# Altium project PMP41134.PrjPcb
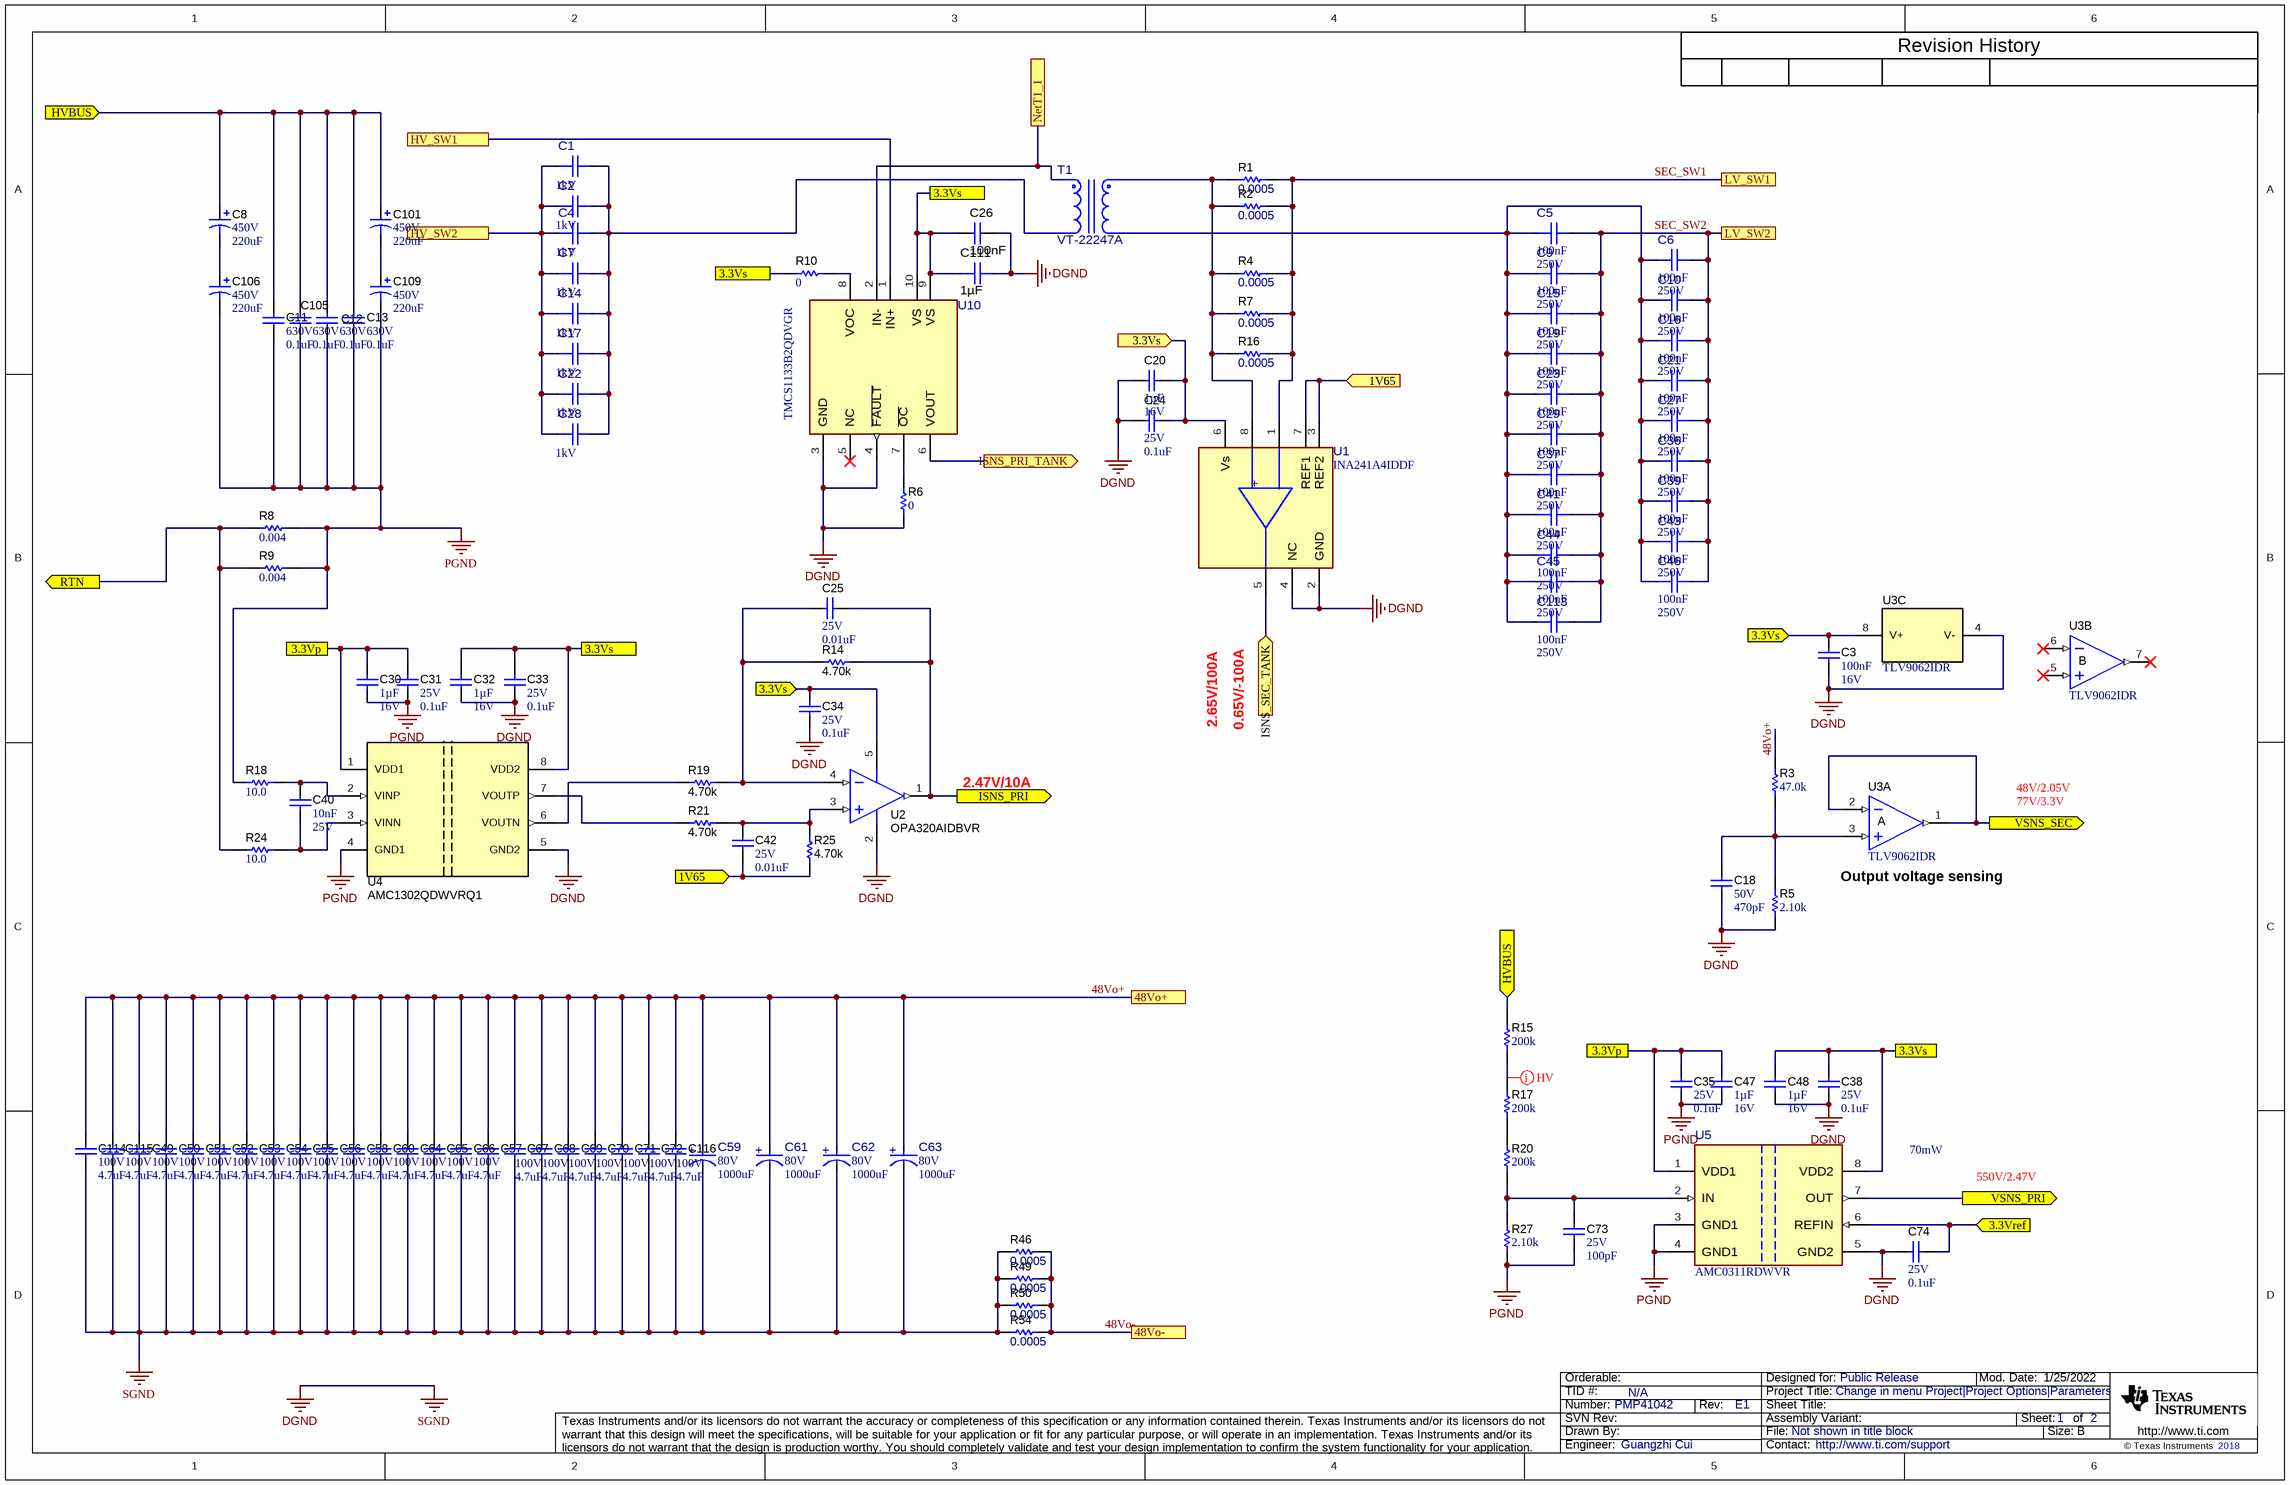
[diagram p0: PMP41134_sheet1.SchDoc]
CopyrightYear: 2018; PCB_Layout: Who did the Layout?; PCB_Rev: E1; PRJ_Customer: Public Release; PRJ_Engineer: Guangzhi Cui; PRJ_Number: PMP41042; PRJ_Title: Change in menu Project|Project Options|Parameters; SCH_Rev: E1; TechSupport: http://www.ti.com/support; TID: N/A
2 sheets, 222 parts. Net scope: flat (ports and power ports of the same name join across sheets).
Board file: PMP41134.PcbDoc
Sheets:
  PMP41134_sheet1.SchDoc
  PMP41134_sheet2.SchDoc

## Sheet PMP41134_sheet1.SchDoc
size 431 x 279 mm; Date: Not shown in title block; ApprovedBy: Not shown in title block; CheckedBy: Not shown in title block; Author: Not shown in title block; CompanyName: Not shown in title block; Engineer: Not shown in title block; Organization: Not shown in title block; Address1: Not shown in title block; Address2: Not shown in title block; Address3: Not shown in title block; Address4: Not shown in title block; DocumentNumber: 1; Revision: Use project parameter SCH_Rev; SheetNumber: 1; SheetTotal: 2; PageSetup: Record=PageOptions¦CenterHorizontal=True¦CenterVertical=True¦PrintScale=1.00¦XCorrection=1.00¦YCorrection=1.00¦PrintKind=0¦BorderSize=5000000¦LeftOffset=0¦BottomOffset=0¦Orientation=2¦PaperLength=1000¦PaperWidth=1000¦Scale=100¦PaperSource=15¦PrintQuality=600¦MediaType=1¦DitherType=10¦PaperKind=Letter¦PrintScaleMode=1

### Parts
C1  VDC_V: 1kV  [FP-C3225C0G3A472J200AC_1210-MFG]  (hidden comment: C3225C0G3A103J250AC)
C2  VDC_V: 1kV  [FP-C3225C0G3A472J200AC_1210-MFG]  (hidden comment: C3225C0G3A103J250AC)
C3  Cap_F: 100nF  VDC_V: 16V  [0603]  (hidden comment: CL10B104KO8NNNC)
C4  VDC_V: 1kV  [FP-C3225C0G3A472J200AC_1210-MFG]  (hidden comment: C3225C0G3A103J250AC)
C5  ValueDisplayed: 100nF  VDC_V: 250V  [FP-C4532C0G2E104J320KN_1812-MFG]  (hidden comment: C4532C0G2E104J320KN)
C6  ValueDisplayed: 100nF  VDC_V: 250V  [FP-C4532C0G2E104J320KN_1812-MFG]  (hidden comment: C4532C0G2E104J320KN)
C7  VDC_V: 1kV  [FP-C3225C0G3A472J200AC_1210-MFG]  (hidden comment: C3225C0G3A103J250AC)
C8  VDC_V: 450V  ValueDisplayed: 220uF  [QXW_1800x5000]  (hidden comment: 450QXW220MEFC18X50)
C9  ValueDisplayed: 100nF  VDC_V: 250V  [FP-C4532C0G2E104J320KN_1812-MFG]  (hidden comment: C4532C0G2E104J320KN)
C10  ValueDisplayed: 100nF  VDC_V: 250V  [FP-C4532C0G2E104J320KN_1812-MFG]  (hidden comment: C4532C0G2E104J320KN)
C11  VDC_V: 630V  ValueDisplayed: 0.1uF  [1210_200]  (hidden comment: CGA6L1X7T2J104K160AC)
C12  VDC_V: 630V  ValueDisplayed: 0.1uF  [1210_200]  (hidden comment: CGA6L1X7T2J104K160AC)
C13  VDC_V: 630V  ValueDisplayed: 0.1uF  [1210_200]  (hidden comment: CGA6L1X7T2J104K160AC)
C14  VDC_V: 1kV  [FP-C3225C0G3A472J200AC_1210-MFG]  (hidden comment: C3225C0G3A103J250AC)
C15  ValueDisplayed: 100nF  VDC_V: 250V  [FP-C4532C0G2E104J320KN_1812-MFG]  (hidden comment: C4532C0G2E104J320KN)
C16  ValueDisplayed: 100nF  VDC_V: 250V  [FP-C4532C0G2E104J320KN_1812-MFG]  (hidden comment: C4532C0G2E104J320KN)
C17  VDC_V: 1kV  [FP-C3225C0G3A472J200AC_1210-MFG]  (hidden comment: C3225C0G3A103J250AC)
C18  VDC_V: 50V  ValueDisplayed: 470pF  [0402]  (hidden comment: GRM1555C1H471JA01D)
C19  ValueDisplayed: 100nF  VDC_V: 250V  [FP-C4532C0G2E104J320KN_1812-MFG]  (hidden comment: C4532C0G2E104J320KN)
C20  Cap_F: 1µF  VDC_V: 16V  [0603]  (hidden comment: CGA3E1X7R1C105K080AC)
C21  ValueDisplayed: 100nF  VDC_V: 250V  [FP-C4532C0G2E104J320KN_1812-MFG]  (hidden comment: C4532C0G2E104J320KN)
C22  VDC_V: 1kV  [FP-C3225C0G3A472J200AC_1210-MFG]  (hidden comment: C3225C0G3A332J200AE)
C23  ValueDisplayed: 100nF  VDC_V: 250V  [FP-C4532C0G2E104J320KN_1812-MFG]  (hidden comment: C4532C0G2E104J320KN)
C24  VDC_V: 25V  ValueDisplayed: 0.1uF  [0402]  (hidden comment: GRM155R71E104KE14D)
C25  VDC_V: 25V  ValueDisplayed: 0.01uF  [0402]  (hidden comment: GCM155R71E103KA37D)
C26  Cap_F: 100nF  [0603]  (hidden comment: 06033C104KAT2A)
C27  ValueDisplayed: 100nF  VDC_V: 250V  [FP-C4532C0G2E104J320KN_1812-MFG]  (hidden comment: C4532C0G2E104J320KN)
C28  VDC_V: 1kV  [FP-C3225C0G3A472J200AC_1210-MFG]  (hidden comment: C3225C0G3A332J200AE)
C29  ValueDisplayed: 100nF  VDC_V: 250V  [FP-C4532C0G2E104J320KN_1812-MFG]  (hidden comment: C4532C0G2E104J320KN)
C30  Cap_F: 1µF  VDC_V: 16V  [0603]  (hidden comment: CGA3E1X7R1C105K080AC)
C31  VDC_V: 25V  ValueDisplayed: 0.1uF  [0402]  (hidden comment: GRM155R71E104KE14D)
C32  Cap_F: 1µF  VDC_V: 16V  [0603]  (hidden comment: CGA3E1X7R1C105K080AC)
C33  VDC_V: 25V  ValueDisplayed: 0.1uF  [0402]  (hidden comment: GRM155R71E104KE14D)
C34  VDC_V: 25V  ValueDisplayed: 0.1uF  [0402]  (hidden comment: GRM155R71E104KE14D)
C35  VDC_V: 25V  ValueDisplayed: 0.1uF  [0402]  (hidden comment: GRM155R71E104KE14D)
C36  ValueDisplayed: 100nF  VDC_V: 250V  [FP-C4532C0G2E104J320KN_1812-MFG]  (hidden comment: C4532C0G2E104J320KN)
C37  ValueDisplayed: 100nF  VDC_V: 250V  [FP-C4532C0G2E104J320KN_1812-MFG]  (hidden comment: C4532C0G2E104J320KN)
C38  VDC_V: 25V  ValueDisplayed: 0.1uF  [0402]  (hidden comment: GRM155R71E104KE14D)
C39  ValueDisplayed: 100nF  VDC_V: 250V  [FP-C4532C0G2E104J320KN_1812-MFG]  (hidden comment: C4532C0G2E104J320KN)
C40  Cap_F: 10nF  VDC_V: 25V  [0603]  (hidden comment: GRM188R71E103KA01D)
C41  ValueDisplayed: 100nF  VDC_V: 250V  [FP-C4532C0G2E104J320KN_1812-MFG]  (hidden comment: C4532C0G2E104J320KN)
C42  VDC_V: 25V  ValueDisplayed: 0.01uF  [0402]  (hidden comment: GCM155R71E103KA37D)
C43  ValueDisplayed: 100nF  VDC_V: 250V  [FP-C4532C0G2E104J320KN_1812-MFG]  (hidden comment: C4532C0G2E104J320KN)
C44  ValueDisplayed: 100nF  VDC_V: 250V  [FP-C4532C0G2E104J320KN_1812-MFG]  (hidden comment: C4532C0G2E104J320KN)
C45  ValueDisplayed: 100nF  VDC_V: 250V  [FP-C4532C0G2E104J320KN_1812-MFG]  (hidden comment: C4532C0G2E104J320KN)
C46  ValueDisplayed: 100nF  VDC_V: 250V  [FP-C4532C0G2E104J320KN_1812-MFG]  (hidden comment: C4532C0G2E104J320KN)
C47  Cap_F: 1µF  VDC_V: 16V  [0603]  (hidden comment: CGA3E1X7R1C105K080AC)
C48  Cap_F: 1µF  VDC_V: 16V  [0603]  (hidden comment: CGA3E1X7R1C105K080AC)
C49  VDC_V: 100V  ValueDisplayed: 4.7uF  [1206_180]  (hidden comment: GRM31CZ72A475KE11L)
C50  VDC_V: 100V  ValueDisplayed: 4.7uF  [1206_180]  (hidden comment: GRM31CZ72A475KE11L)
C51  VDC_V: 100V  ValueDisplayed: 4.7uF  [1206_180]  (hidden comment: GRM31CZ72A475KE11L)
C52  VDC_V: 100V  ValueDisplayed: 4.7uF  [1206_180]  (hidden comment: GRM31CZ72A475KE11L)
C53  VDC_V: 100V  ValueDisplayed: 4.7uF  [1206_180]  (hidden comment: GRM31CZ72A475KE11L)
C54  VDC_V: 100V  ValueDisplayed: 4.7uF  [1206_180]  (hidden comment: GRM31CZ72A475KE11L)
C55  VDC_V: 100V  ValueDisplayed: 4.7uF  [1206_180]  (hidden comment: GRM31CZ72A475KE11L)
C56  VDC_V: 100V  ValueDisplayed: 4.7uF  [1206_180]  (hidden comment: GRM31CZ72A475KE11L)
C57  GRM31CR72A225KA73L  [1206_190]  (value not drawn)
C58  VDC_V: 100V  ValueDisplayed: 4.7uF  [1206_180]  (hidden comment: GRM31CZ72A475KE11L)
C59  VDC_V: 80V  ValueDisplayed: 1000uF  [FP-EGPD800ELL102ML35H_RADIAL-MFG]  (hidden comment: EGPD800ELL102ML35H)
C60  VDC_V: 100V  ValueDisplayed: 4.7uF  [1206_180]  (hidden comment: GRM31CZ72A475KE11L)
C61  VDC_V: 80V  ValueDisplayed: 1000uF  [FP-EGPD800ELL102ML35H_RADIAL-MFG]  (hidden comment: EGPD800ELL102ML35H)
C62  VDC_V: 80V  ValueDisplayed: 1000uF  [FP-EGPD800ELL102ML35H_RADIAL-MFG]  (hidden comment: EGPD800ELL102ML35H)
C63  VDC_V: 80V  ValueDisplayed: 1000uF  [FP-EGPD800ELL102ML35H_RADIAL-MFG]  (hidden comment: EGPD800ELL102ML35H)
C64  VDC_V: 100V  ValueDisplayed: 4.7uF  [1206_180]  (hidden comment: GRM31CZ72A475KE11L)
C65  VDC_V: 100V  ValueDisplayed: 4.7uF  [1206_180]  (hidden comment: GRM31CZ72A475KE11L)
C66  VDC_V: 100V  ValueDisplayed: 4.7uF  [1206_180]  (hidden comment: GRM31CZ72A475KE11L)
C67  VDC_V: 100V  ValueDisplayed: 4.7uF  [1206_180]  (hidden comment: GRM31CZ72A475KE11L)
C68  VDC_V: 100V  ValueDisplayed: 4.7uF  [1206_180]  (hidden comment: GRM31CZ72A475KE11L)
C69  VDC_V: 100V  ValueDisplayed: 4.7uF  [1206_180]  (hidden comment: GRM31CZ72A475KE11L)
C70  VDC_V: 100V  ValueDisplayed: 4.7uF  [1206_180]  (hidden comment: GRM31CZ72A475KE11L)
C71  VDC_V: 100V  ValueDisplayed: 4.7uF  [1206_180]  (hidden comment: GRM31CZ72A475KE11L)
C72  VDC_V: 100V  ValueDisplayed: 4.7uF  [1206_180]  (hidden comment: GRM31CZ72A475KE11L)
C73  VDC_V: 25V  ValueDisplayed: 100pF  [0402]  (hidden comment: C0402C101J3GACTU)
C74  VDC_V: 25V  ValueDisplayed: 0.1uF  [0402]  (hidden comment: GRM155R71E104KE14D)
C101  VDC_V: 450V  ValueDisplayed: 220uF  [QXW_1800x5000]  (hidden comment: 450QXW220MEFC18X50)
C105  VDC_V: 630V  ValueDisplayed: 0.1uF  [1210_200]  (hidden comment: CGA6L1X7T2J104K160AC)
C106  VDC_V: 450V  ValueDisplayed: 220uF  [QXW_1800x5000]  (hidden comment: 450QXW220MEFC18X50)
C109  VDC_V: 450V  ValueDisplayed: 220uF  [QXW_1800x5000]  (hidden comment: 450QXW220MEFC18X50)
C111  Cap_F: 1µF  [FP-CL10B105KA8VPJC_0603-MFG]  (hidden comment: CL10B105KA8VPJC)
C113  ValueDisplayed: 100nF  VDC_V: 250V  [FP-C4532C0G2E104J320KN_1812-MFG]  (hidden comment: C4532C0G2E104J320KN)
C114  VDC_V: 100V  ValueDisplayed: 4.7uF  [1206_180]  (hidden comment: GRM31CZ72A475KE11L)
C115  VDC_V: 100V  ValueDisplayed: 4.7uF  [1206_180]  (hidden comment: GRM31CZ72A475KE11L)
C116  VDC_V: 100V  ValueDisplayed: 4.7uF  [1206_180]  (hidden comment: GRM31CZ72A475KE11L)
R1  ValueDisplayed: 0.0005  [2512]  (hidden comment: CSNL2512FTL500)
R2  ValueDisplayed: 0.0005  [2512]  (hidden comment: CSNL2512FTL500)
R3  ValueDisplayed: 47.0k  [0603]  (hidden comment: CRCW060347K0FKEA)
R4  ValueDisplayed: 0.0005  [2512]  (hidden comment: CSNL2512FTL500)
R5  ValueDisplayed: 2.10k  [0603]  (hidden comment: RT0603BRD072K1L)
R6  ValueDisplayed: 0  [0603]  (hidden comment: MCT06030Z0000ZP500)
R7  ValueDisplayed: 0.0005  [2512]  (hidden comment: CSNL2512FTL500)
R8  ValueDisplayed: 0.004  [1206]  (hidden comment: CRF1206-FZ-R004ELF)
R9  ValueDisplayed: 0.004  [1206]  (hidden comment: CRF1206-FZ-R004ELF)
R10  ValueDisplayed: 0  [0603]  (hidden comment: MCT06030Z0000ZP500)
R14  ValueDisplayed: 4.70k  [0402]  (hidden comment: RC0402FR-074K7L)
R15  ValueDisplayed: 200k  [1206]  (hidden comment: ERJ-8ENF2003V)
R16  ValueDisplayed: 0.0005  [2512]  (hidden comment: CSNL2512FTL500)
R17  ValueDisplayed: 200k  [1206]  (hidden comment: ERJ-8ENF2003V)
R18  ValueDisplayed: 10.0  [0603]  (hidden comment: CRCW060310R0FKEA)
R19  ValueDisplayed: 4.70k  [0402]  (hidden comment: RC0402FR-074K7L)
R20  ValueDisplayed: 200k  [1206]  (hidden comment: ERJ-8ENF2003V)
R21  ValueDisplayed: 4.70k  [0402]  (hidden comment: RC0402FR-074K7L)
R24  ValueDisplayed: 10.0  [0603]  (hidden comment: CRCW060310R0FKEA)
R25  ValueDisplayed: 4.70k  [0402]  (hidden comment: RC0402FR-074K7L)
R27  ValueDisplayed: 2.10k  [0603]  (hidden comment: RT0603BRD072K1L)
R46  ValueDisplayed: 0.0005  [2512]  (hidden comment: CSNL2512FTL500)
R49  ValueDisplayed: 0.0005  [2512]  (hidden comment: CSNL2512FTL500)
R50  ValueDisplayed: 0.0005  [2512]  (hidden comment: CSNL2512FTL500)
R54  ValueDisplayed: 0.0005  [2512]  (hidden comment: CSNL2512FTL500)
T1  VT-22247A  [FP-VT-22247A_XFRMR_70MM0_63MM0-MFG]
U1  INA241A4IDDF  [DDF0008A-MFG]
U2  OPA320AIDBVR  [DBV0005A_N]
U3  TLV9062IDR  [D0008A_N]  (parts A,B,C of 3)
U4  AMC1302QDWVRQ1  [DWV0008A]
U5  AMC0311RDWVR  [DWV0008A-MFG]
U10  TMCS1133B2QDVGR  [DVG0010A-MFG]

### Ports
1V65 (in), 3.3Vp, 3.3Vref (in), 3.3Vs, 3.3Vs (in), 48Vo+, 48Vo-, HV_SW1, HV_SW2, HVBUS (in), ISNS_PRI (out), ISNS_PRI_TANK (out), ISNS_SEC_TANK (in), LV_SW1, LV_SW2, NetT1_1, RTN (out), VSNS_PRI (out), VSNS_SEC (out)

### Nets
PGND: C11.2 C12.2 C13.2 C30.2 C31.2 C35.2 C47.2 C73.2 C105.2 C106.2(-) C109.2(-) R8.2 R9.2 R18.1 R27.1 U4.4(GND1) U5.3(GND1) U5.4(GND1)
SGND: C3.2 C18.2 C20.2 C24.2 C26.2 C32.2 C33.2 C34.2 C38.2 C48.2 C49.2 C50.2 C51.2 C52.2 C53.2 C54.2 C55.2 C56.2 C57.2 C58.2 C59.1(CATHODE) C60.2 C61.1(CATHODE) C62.1(CATHODE) C63.1(CATHODE) C64.2 C65.2 C66.2 C67.2 C68.2 C69.2 C70.2 C71.2 C72.2 C74.1 C111.2 C114.2 C115.2 C116.2 R5.1 R6.1 R46.1 R49.1 R50.1 R54.1 U1.2(GND) U1.4(NC) U2.2(V-) U3.4(V-) U4.5(GND2) U5.5(GND2) U10.3(GND) U10.4(~{FAULT})  [also labelled DGND]
1V65: C42.2 R25.1 U1.3(REF2) U1.7(REF1) ; port 1V65
3.3Vp: C30.1 C31.1 C35.1 C47.1 U4.1(VDD1) U5.1(VDD1) ; port 3.3Vp
3.3Vref: C74.2 U5.6(REFIN) ; port 3.3Vref
3.3Vs: C3.1 C20.1 C24.1 C26.1 C32.1 C33.1 C34.1 C38.1 C48.1 C111.1 R10.2 U1.6(Vs) U2.5(V+) U3.8(V+) U4.8(VDD2) U5.8(VDD2) U10.9(VS) U10.10(VS) ; port 3.3Vs
48Vo+: C49.1 C50.1 C51.1 C52.1 C53.1 C54.1 C55.1 C56.1 C57.1 C58.1 C59.2(ANODE) C60.1 C61.2(ANODE) C62.2(ANODE) C63.2(ANODE) C64.1 C65.1 C66.1 C67.1 C68.1 C69.1 C70.1 C71.1 C72.1 C114.1 C115.1 C116.1 R3.2 ; port 48Vo+
48Vo-: R46.2 R49.2 R50.2 R54.2 ; port 48Vo-
HV_SW1: U10.1(IN+) ; port HV_SW1
HV_SW2: C1.1 C2.1 C4.1 C7.1 C14.1 C17.1 C22.1 C28.1 ; port HV_SW2
HVBUS: C8.1(+) C11.1 C12.1 C13.1 C101.1(+) C105.1 R15.2 ; port HVBUS
ISNS_PRI: C25.1 R14.2 U2.1(OUT) ; port ISNS_PRI
ISNS_PRI_TANK: U10.6(VOUT) ; port ISNS_PRI_TANK
ISNS_SEC_TANK: U1.5(OUT) ; port ISNS_SEC_TANK
NetT1_1: U10.2(IN-) ; port NetT1_1
RTN: R8.1 R9.1 R24.1 ; port RTN
SEC_SW1: R1.2 R2.2 R4.2 R7.2 R16.2 U1.1(IN-) ; port LV_SW1
SEC_SW2: C5.2 C6.2 C9.2 C10.2 C15.2 C16.2 C19.2 C21.2 C23.2 C27.2 C29.2 C36.2 C37.2 C39.2 C41.2 C43.2 C44.2 C45.2 C46.2 C113.2 ; port LV_SW2
VSNS_PRI: U5.7(OUT) ; port VSNS_PRI
VSNS_SEC: U3.1(OUT) U3.2(IN-) ; port VSNS_SEC
NetC1_2: C1.2 C2.2 C4.2 C7.2 C14.2 C17.2 C22.2 C28.2
NetC5_1: C5.1 C6.1 C9.1 C10.1 C15.1 C16.1 C19.1 C21.1 C23.1 C27.1 C29.1 C36.1 C37.1 C39.1 C41.1 C43.1 C44.1 C45.1 C46.1 C113.1
NetC8_2: C8.2(-) C106.1(+)
NetC18_1: C18.1 R3.1 R5.2 U3.3(IN+)
NetC25_2: C25.2 R14.1 R19.2 U2.4(IN-)
NetC40_1: C40.1 R18.2 U4.2(VINP)
NetC40_2: C40.2 R24.2 U4.3(VINN)
NetC42_1: C42.1 R21.2 R25.2 U2.3(IN+)
NetC73_1: C73.1 R20.1 R27.2 U5.2(IN)
NetC101_2: C101.2(-) C109.1(+)
NetR1_1: R1.1 R2.1 R4.1 R7.1 R16.1 U1.8(IN+)
NetR6_2: R6.2 U10.7(~{OC})
NetR10_1: R10.1 U10.8(VOC)
NetR15_1: R15.1 R17.2
NetR17_1: R17.1 R20.2
NetR19_1: R19.1 U4.6(VOUTN)
NetR21_1: R21.1 U4.7(VOUTP)

Not connected (* = marked no-connect by the designer): U3 5(IN+)* 6(IN-)* 7(OUT)*; U10 5(NC)*

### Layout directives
net class MV: NetR15_1

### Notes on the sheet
- Revision History
- 2.65V/100A
- 0.65V/-100A
- 2.47V/10A
- 77V/3.3V
- 48V/2.05V
- (near U3) Output voltage sensing
- 70mW
- 550V/2.47V

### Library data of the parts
C1 C2 C4 C7 C14 C17 = CMP-0121422-1: Multilayer Ceramic Capacitors 10nF ±5% 1000V C0G SMD 1210; Manufacturer: TDK; AEC Qualified: No; SizeZ_mm: 2.2mm; TempCo: 30ppm/°C; Tolerance_%: 0.05%
C3 = CMP-0007110-5: CAP, CERM, 0.1 uF, 16 V, +/- 10%, X7R, 0603; Manufacturer: Samsung Electro-Mechanics; TaMin_C: -55°C; Polarized: N; SizeAreaWB_mm2: 4.68; Value1: Unknown; U/M: EA; Value: 0.1uF; TaMax_C: 125°C; SizeZ_mm: 1; SizeX_mm: 1.6; SizeY_mm: 0.8; SizeArea_mm2: 1.28; AEC Category: Q200
C5 C6 C9 C10 C15 C16 C19 C21 C23 C27 C29 C36 C37 C39 C41 C43-C46 C113 = CMP-0097363-1: Multilayer Ceramic Capacitors 100nF ±5% 250V C0G SMD 1812; Manufacturer: TDK; SizeZ_mm: 3.5mm; TempCo: 30ppm/°C; Tolerance_%: 0.05%; AEC Qualified: No
C8 C101 C106 C109 = CMP-0009981-2: CAP, AL, 220 uF, 450 V, +/- 20%, TH; Manufacturer: Rubycon; TaMin_C: -40°C; Polarized: Y; SizeAreaWB_mm2: 400; Value1: Unknown; U/M: EA; Value: 220uF; TaMax_C: 105°C; SizeZ_mm: 52; SizeX_mm: 18; Cap_Case: 18x50mm; SizeArea_mm2: 324; CompType: Capacitor; AEC Qualified: N; Cap_F: 220µF; IRMS_A: 1.22A; AEC Category: Q200
C11-C13 C105 = CMP-0009140-2: CAP, CERM, 0.1 uF, 630 V, +/- 10%, X7R, AEC-Q200 Grade 1, 1210; Manufacturer: TDK; TaMin_C: -55°C; Polarized: N; SizeAreaWB_mm2: 14.7; Value1: Unknown; U/M: EA; Value: 0.1uF; TaMax_C: 125°C; SizeZ_mm: 2; SizeX_mm: 3.2; SizeY_mm: 2.5; Cap_Case: 1210; SizeArea_mm2: 8; AEC Qualified: Y; Cap_F: 100nF; AEC Grade: 1; AEC Category: Q200
C18 = CMP-0006470-1: CAP, CERM, 470 pF, 50 V, +/- 5%, C0G/NP0, 0402; Manufacturer: MuRata; TaMin_C: -55°C; Polarized: N; SizeAreaWB_mm2: 3; Value1: Unknown; U/M: EA; Value: 470pF; TaMax_C: 125°C; SizeZ_mm: 0.6; SizeX_mm: 1; SizeY_mm: 0.5; AEC Category: Q200
C20 C30 C32 C47 C48 = CMP-0079607-1: CAP, CERM, 1 µF, 16 V,+/- 10%, X7R, AEC-Q200 Grade 1, 0603; Manufacturer: TDK; TaMin_C: -55°C; Polarized: N; SizeAreaWB_mm2: 4.68; U/M: EA; Value: 1uF; TaMax_C: 125°C; SizeZ_mm: 1; SizeX_mm: 1.6; SizeY_mm: 0.8; SizeArea_mm2: 1.28; AEC Qualified: Y; AEC Category: Q200
C22 = CMP-0121422-1: Multilayer Ceramic Capacitors 3.3nF ±5% 1000V C0G SMD 1210; Manufacturer: TDK; AEC Qualified: No; SizeZ_mm: 2.2mm; TempCo: 30ppm/°C; Tolerance_%: 0.05%
C24 C31 C33-C35 C38 C74 = CMP-0006659-2: CAP, CERM, 0.1 uF, 25 V, +/- 10%, X7R, 0402; Manufacturer: MuRata; TaMin_C: -55°C; Polarized: N; SizeAreaWB_mm2: 3; Value1: Unknown; U/M: EA; Value: 0.1uF; TaMax_C: 125°C; SizeZ_mm: 0.6; SizeX_mm: 1; SizeY_mm: 0.5; Cap_F: 100nF; AEC Category: Q200
C25 C42 = CMP-0006352-2: CAP, CERM, 0.01 uF, 25 V, +/- 10%, X7R, 0402; Manufacturer: MuRata; TaMin_C: -55°C; Polarized: N; SizeAreaWB_mm2: 3; Value1: Unknown; U/M: EA; Value: 0.01uF; TaMax_C: 125°C; SizeZ_mm: 0.6; SizeX_mm: 1; SizeY_mm: 0.5; Cap_F: 10nF; AEC Category: Q200
C26 = CMP-0006753-4: CAP, CERM, 0.1 uF, 25 V, +/- 10%, X7R, 0603; Manufacturer: AVX; TaMin_C: -55°C; ESR_ohm: 0.05; Polarized: N; SizeAreaWB_mm2: 4.68; Value1: 0.05 ohm; U/M: EA; Value: 0.1uF; TaMax_C: 125°C; SizeZ_mm: 1; SizeX_mm: 1.6; SizeY_mm: 0.8; Value2: 25V; SizeArea_mm2: 1.28; AEC Category: Q200
C28 = CMP-0121422-1: Multilayer Ceramic Capacitors 3.3nF ±5% 1000V C0G SMD 1210; Manufacturer: TDK; Part Number: C3225C0G3A472J200AC; AEC Qualified: No; Cap_F: 4.7nF; SizeZ_mm: 2.2mm; TempCo: 30ppm/°C; Tolerance_%: 0.05%
C40 = CMP-0007403-4: CAP, CERM, 0.01 uF, 25 V, +/- 10%, X7R, 0603; Manufacturer: MuRata; TaMin_C: -55°C; Polarized: N; SizeAreaWB_mm2: 4.68; Value1: Unknown; U/M: EA; Value: 0.01uF; TaMax_C: 125°C; SizeZ_mm: 1; SizeX_mm: 1.6; SizeY_mm: 0.8; SizeArea_mm2: 1.28; AEC Category: Q200
C49-C56 C58 C60 C64-C72 C114-C116 = CMP-0008802-2: CAP, CERM, 4.7 uF, 100 V, +/- 10%, X7R, 1206; Manufacturer: Samsung; TaMin_C: -55°C; Polarized: N; SizeAreaWB_mm2: 10.92; Value1: Unknown; U/M: EA; Value: 4.7uF; TaMax_C: 125°C; SizeZ_mm: 1.8; SizeX_mm: 3.2; SizeY_mm: 1.6; Cap_Case: 1206; SizeArea_mm2: 5.12; Cap_F: 4.7µF; AEC Category: Q200
C57 = CMP-0008971-1: CAP, CERM, 2.2 uF, 100 V, +/- 10%, X7R, 1206_190; Manufacturer: MuRata; TaMin_C: -55°C; Polarized: N; SizeAreaWB_mm2: 10.92; Value1: Unknown; U/M: EA; Value: 2.2uF; TaMax_C: 125°C; SizeZ_mm: 1.9; SizeX_mm: 3.2; SizeY_mm: 1.6; Cap_Case: 1206; Value2: 100V; SizeArea_mm2: 5.12; Cap_F: 2.2µF; AEC Category: Q200
C59 C61-C63 = CMP-0097417-1: 1000 µF 80 V Aluminum Electrolytic Capacitors Radial, Can 27mOhm @ 100kHz 2000 Hrs @ 135°C; Manufacturer: United Chemi-Con; AEC Grade: Grade 0; Value: 1mF; Leakage Current: 2400uA; AEC Qualified: Yes; IRMS_A: 4.59A; Tolerance_%: 20%; Dissipation Factor: 8%; Life: 2000Hours; SizeZ_mm: 36.5mm; Esr: 27m
C73 = CMP-0006233-2: CAP, CERM, 100 pF, 25 V, +/- 5%, C0G/NP0, 0402; Manufacturer: Kemet; TaMin_C: -55°C; Polarized: N; SizeAreaWB_mm2: 3; Value1: Unknown; U/M: EA; Value: 100pF; TaMax_C: 125°C; SizeZ_mm: 0.6; SizeX_mm: 1; SizeY_mm: 0.5; AEC Category: Q200
C111 = CMP-0121052-1: Cap Ceramic 1uF 25V X7R ±10% Pad SMD 0603 +125°C T/R; Manufacturer: Samsung; AEC Grade: Grade 1; AEC Qualified: Yes; SizeZ_mm: 0.9mm; TempCo: 15%; Value: 1µF
R1 R2 R4 R7 R16 R46 R49 R50 R54 = CMP-0015817-2: RES, 0.0005, 1%, 2 W, 2512; Manufacturer: Stackpole Electronics Inc; Power_W: 3W; TempCo: ppm/C; Value_Code: 1L000; U/M: EA; Value: 0.0005; EIA_Code: E96; Res_ohm: 1m; SizeX_mm: 6.3; SizeY_mm: 3.2; SizeZ_mm: 0.71; Value2: 2W; SizeArea_mm2: 20.16; AEC Category: Q200
R3 = CMP-0022438-1: RES, 47.0 k, 1%, 0.1 W, AEC-Q200 Grade 0, 0603; Manufacturer: Vishay-Dale; Power_W: 100mW; TempCo: 100 ppm/C; Value_Code: 47k0; U/M: EA; Value: 47.0k; Res_ohm: 47k; SizeX_mm: 1.6; SizeY_mm: 0.8; SizeZ_mm: 1; Value2: 0.1W; SizeArea_mm2: 1.28; AEC Qualified: Y; VDC_V: 75V; AEC Grade: 0; AEC Category: Q200
R5 R27 = CMP-0024062-3: RES, 2.10 k, 0.1%, 0.1 W, 0603; Manufacturer: Yageo America; Power_W: 100mW; TempCo: 25 ppm/C; Value_Code: 2k10; U/M: EA; Value: 2.10k; EIA_Code: E192; Res_ohm: 2.1k; SizeX_mm: 1.6; SizeY_mm: 0.8; SizeZ_mm: 1; Value2: 0.1W; SizeArea_mm2: 1.28; VDC_V: 75V; AEC Category: Q200
R6 R10 = CMP-0025884-2: RES, 0, 5%, 0.125 W, 0603; Manufacturer: Vishay/Beyschlag; Power_W: 125mW; TempCo: ppm/C; Value_Code: 0000; U/M: EA; Value: 0; EIA_Code: E24; SizeX_mm: 1.6; SizeY_mm: 0.8; SizeZ_mm: 1; Value2: 0.125W; SizeArea_mm2: 1.28; AEC Qualified: N; AEC Category: Q200
R8 R9 = CMP-0078823-1: RES, 0.004, 1%, 1 W, AEC-Q200 Grade 0, 1206; Manufacturer: Bourns; Value_Code: 4L000; SizeArea_mm2: 5.12; AEC Qualified: Y; AEC Category: Q200; Res_ohm: 4m; Value: 0.004; SizeZ_mm: 1.35; TempCo: 50 ppm/C; AEC Grade: 0; SizeY_mm: 1.6; Power_W: 1W; SizeX_mm: 3.2
R14 R19 R21 R25 = CMP-0026739-1: RES, 4.70 k, 1%, 0.0625 W, 0402; Manufacturer: Yageo America; Power_W: 62.5mW; TempCo: 100 ppm/C; Value_Code: 4k70; U/M: EA; Value: 4.70k; Res_ohm: 4.7k; SizeX_mm: 1; SizeY_mm: 0.5; SizeZ_mm: 0.6; CompType: Resistor; AEC Qualified: N; VDC_V: 50V; AEC Category: Q200
R15 R17 R20 = CMP-0017437-1: RES, 200 k, 1%, 0.25 W, 1206; Manufacturer: Panasonic; Power_W: 250mW; TempCo: 100 ppm/C; U/M: EA; Value: 200k; EIA_Code: E96; SizeX_mm: 3.2; SizeY_mm: 1.6; SizeZ_mm: 1.35; Value2: 0.25W; SizeArea_mm2: 5.12; VDC_V: 200V; AEC Category: Q200
R18 R24 = CMP-0022003-4: RES, 10.0, 1%, 0.1 W, AEC-Q200 Grade 0, 0603; Manufacturer: Vishay-Dale; Power_W: 100mW; TempCo: 100 ppm/C; Value_Code: 10R0; Value: 10.0; EIA_Code: E96; Res_ohm: 10; SizeX_mm: 1.6; SizeY_mm: 0.8; SizeZ_mm: 1; Value2: 0.1W; SizeArea_mm2: 1.28; AEC Qualified: Y; VDC_V: 75V; AEC Category: Q200; AEC Grade: 0
T1 = CMP-0097657-1: Transformer 25:3 70x63x51mm; Manufacturer: Cyntec; SizeZ_mm: 51mm; DCR_ohm: 27m; Rsec1_ohm: 850µ; AEC Qualified: No; Ind_H: 47.4µH
U1 = CMP-0093650-2: -4-V to 110-V, Bidirectional, Ultra-Precise Current Sense Amplifier With Enhanced PWM Rejection; Manufacturer: Texas Instruments; Input Bias Current: 40uA; Response Time: 1.5us; TaMax_C: +125°C; Min Supply Voltage: 2.7V; Bandwidth: 1MHz; SizeZ_mm: 1.1mm; Number Of Channels: 1; Standoff Height: 0mm; Max Supply Voltage: 20V; Input Offset Voltage: 0.002mV; TJmax_C: +150°C; AEC Category: Q200; CompType: IC; TaMin_C: -40°C; Voltage Gain: 0.1V/mV; AEC Qualified: No; Nominal Supply Current: 2.5mA
U2 = CMP-0040888-1: Precision, 20 MHz, 0.9 pA Ib, RRIO, CMOS Operational Amplifier, 1.8 to 5.5 V, -40 to 125 degC, 5-pin SOT23 (DBV5), Green (RoHS & no Sb/Br); Manufacturer: Texas Instruments; CMRR(Min)(dB): 100; Iq per channel(Max)(mA): 1.75; IIB(Max)(pA): 0.9; Total Supply Voltage(Min)(+5V is 5, +/-5V is 10): 1.8; Sub Family: High Output Current Amplifier (>=50mA), Low Input Bias Current Amp (<=10pA), Low Noise Amp (<=10nV/rtHz), Low Offset Voltage Amplifier (<=500uV), Low Supply Voltage Amplifier (<=2.7V), Precision Amplifier; Number of Channels: 2; Total Supply Voltage(Max)(+5V is 5, +/-5V is 10): 5.5; Offset Drift(Typ)(uV/C): 1.5; Vn at 1kHz(Typ)(nV/rtHz): 8.5; Slew Rate(Typ)(V/us): 10; Vio (25C)(Max)(mV): 0.15
U3 = CMP-0013007-4: 10-MHz, Low-Noise, RRIO, CMOS Operational Amplifier for Cost-Sensitive Systems, D0008A (SOIC-8); Manufacturer: Texas Instruments; SizeX_mm: 4.9; SizeY_mm: 6.2; CompType: IC; SizeZ_mm: 1.75; SizeArea_mm2: 30.38; SizeAreaWB_mm2: 56.58; AEC Category: Q200; AEC Qualified: N; Rating: Catalog
U4 = CMP-0080587-1: Precision Reinforced Isolated Amplifier for Current Sensing, DWV0008A (SOIC-8); Alternate Manufacturer: Texas Instruments; SizeAreaWB_mm2: 105.975; SizeZ_mm: 2.8; SizeX_mm: 11.5; SizeY_mm: 5.85; SizeArea_mm2: 67.275; CompType: IC; AEC Qualified: Y; AEC Category: Q200
U5 = CMP-0122957-1: Automotive, Precision, 2-V Input, Basic and Reinforced Isolated Amplifiers With Single-Ended, Ratiometric Output; Manufacturer: Texas Instruments; SizeZ_mm: 2.8mm; AEC Qualified: No; Bandwidth: 110kHz; Input Bias Current: 0.0035uA; Input Offset Voltage: 0.4mV; Max Supply Voltage: 5.5V; Min Supply Voltage: 3V; Number Of Channels: 1; Output Current Per Channel: 14mA; Response Time: 500us; Standoff Height: 0.36mm; TaMax_C: +125°C; TaMin_C: -40°C; TJmax_C: +150°C
U10 = CMP-0097985-1: Manufacturer: Texas Instruments; SizeZ_mm: 2.65mm; Standoff Height: 0.1mm

## Sheet PMP41134_sheet2.SchDoc
size A2; SheetNumber: 2; SheetTotal: 2
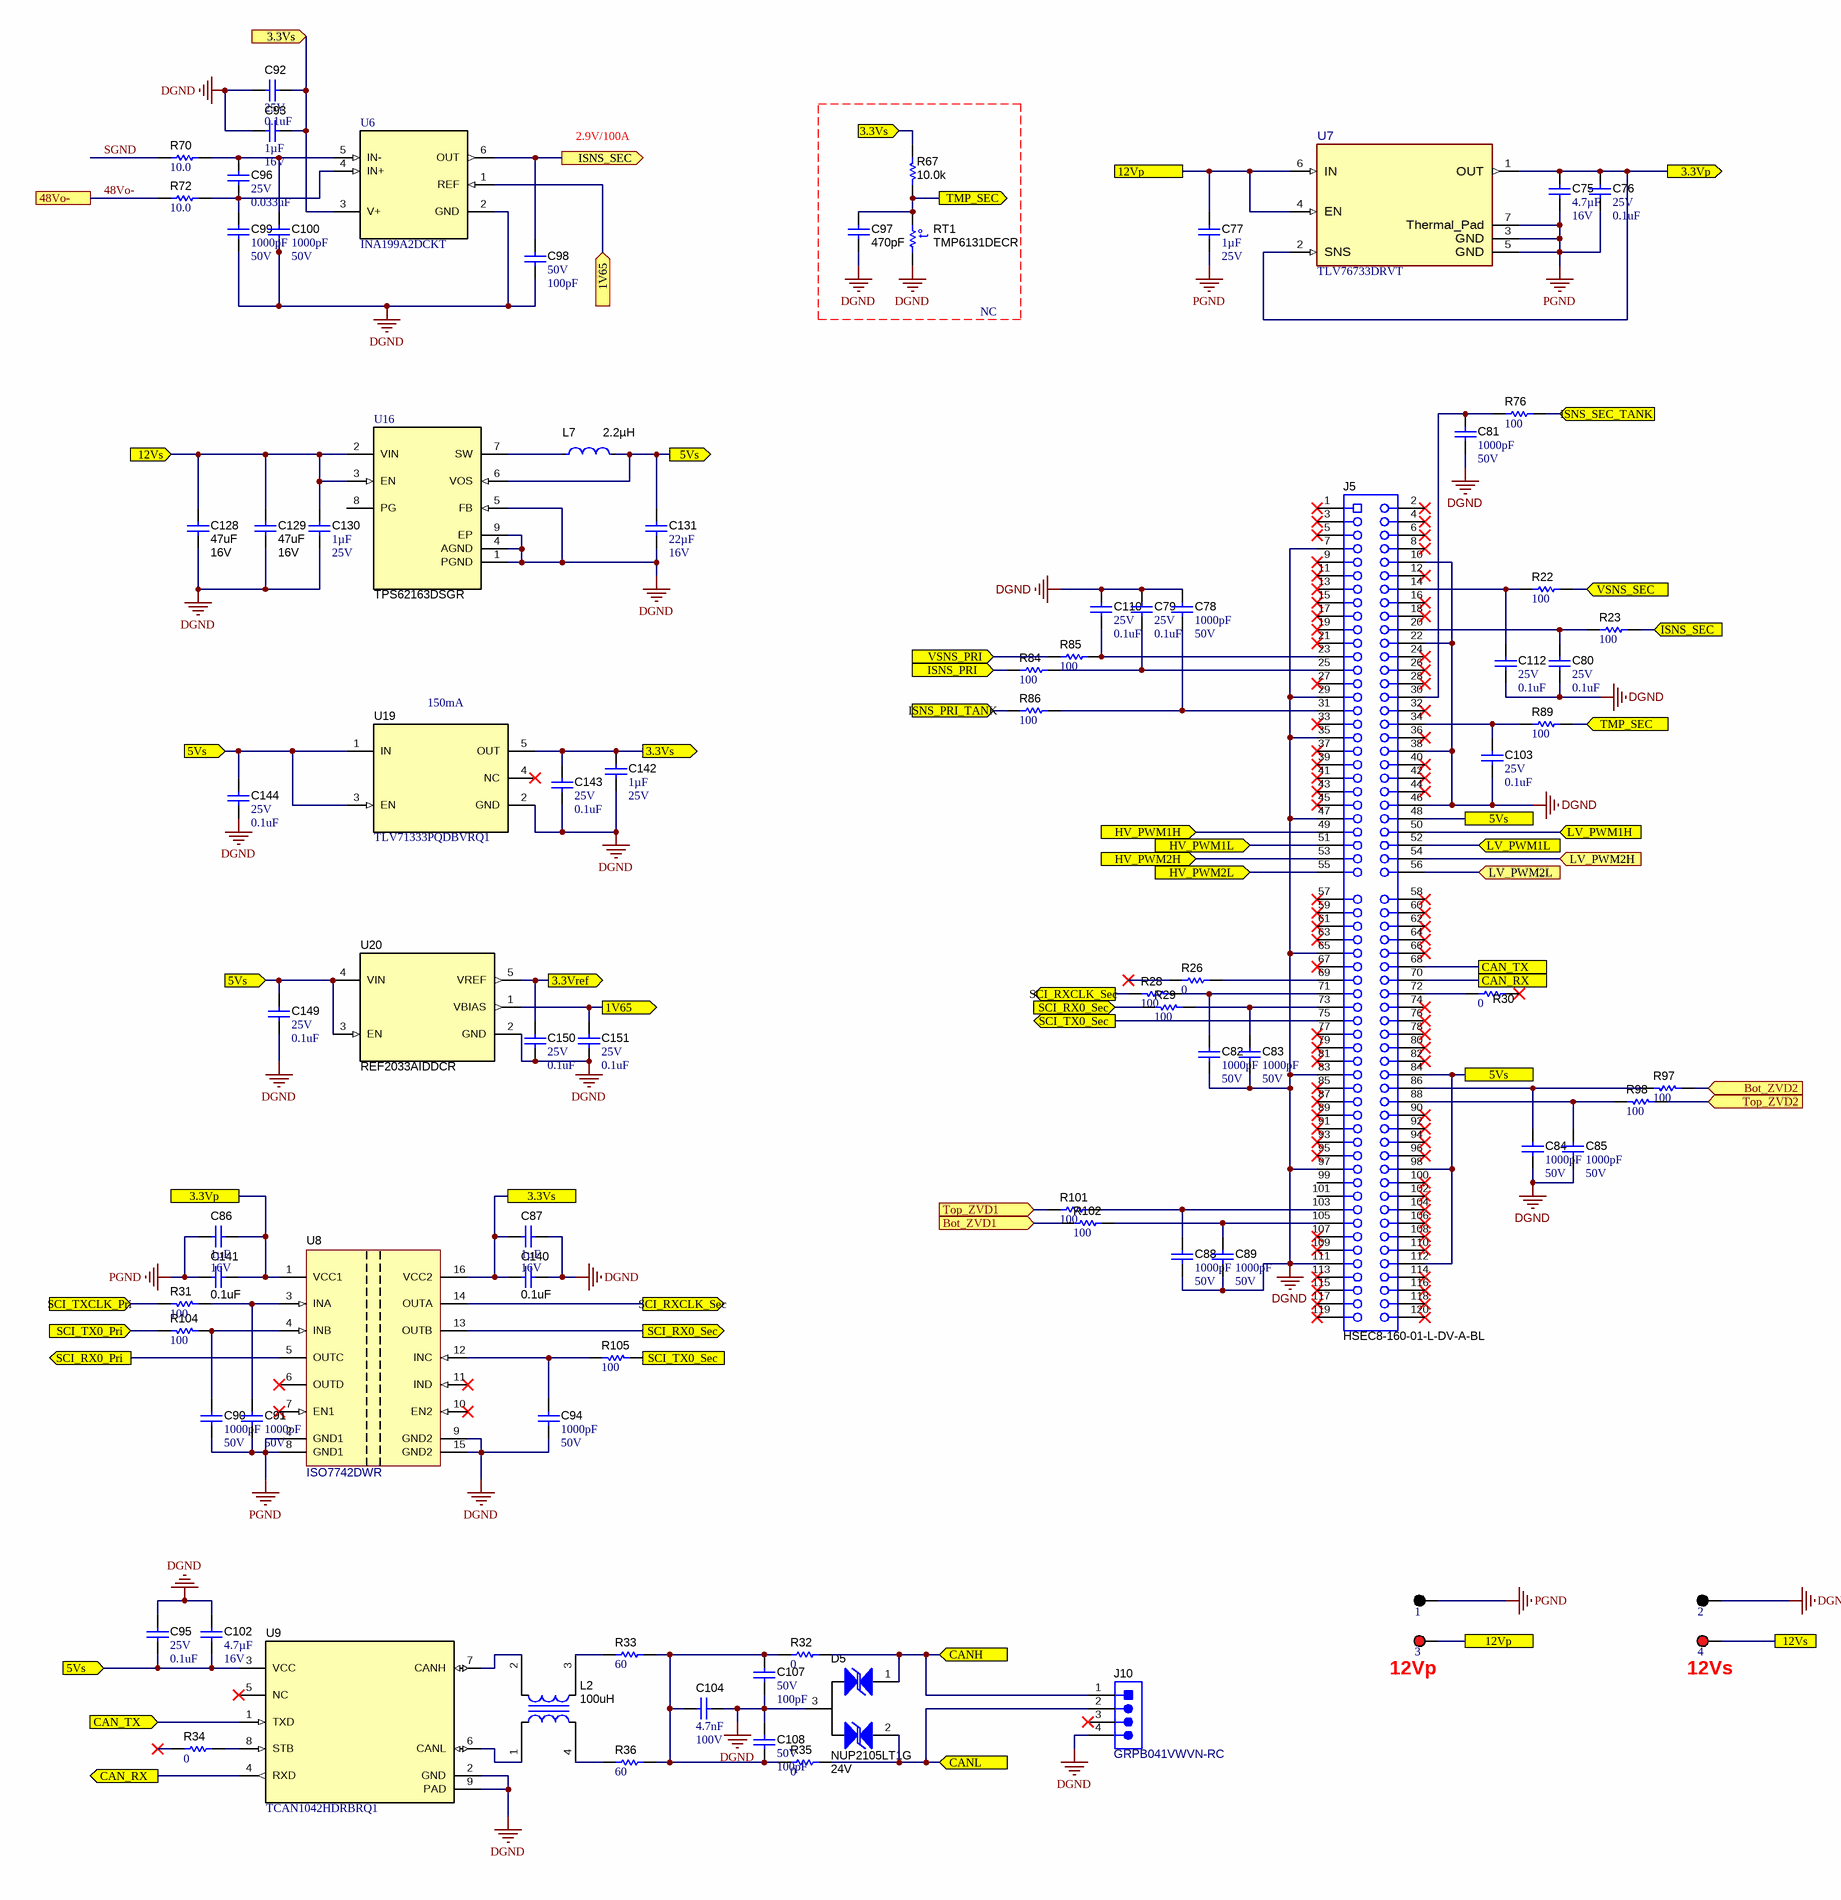
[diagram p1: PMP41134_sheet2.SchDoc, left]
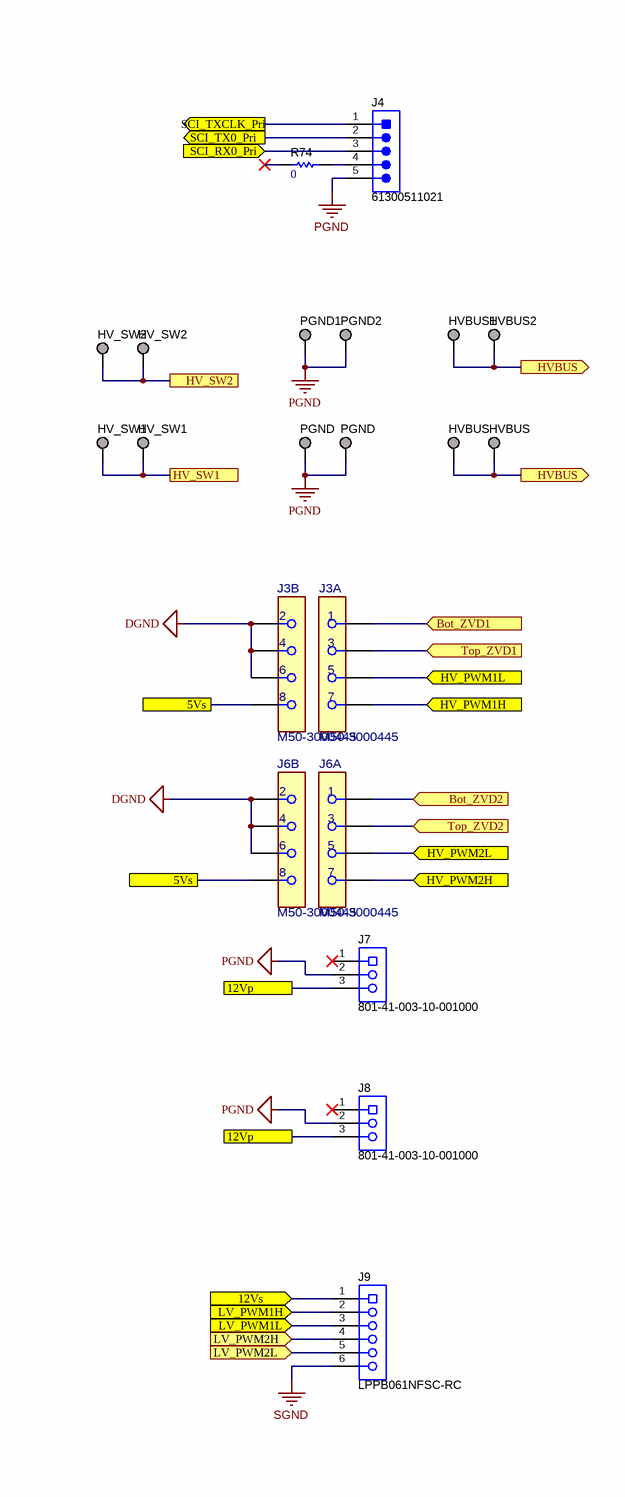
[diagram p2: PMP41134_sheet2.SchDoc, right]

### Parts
(Parts that share a designator on the sheet are numbered #1, #2 ... from top to bottom, then left to right.)
1  5001  [Keystone5001]  (value not drawn)
2  5001  [Keystone5001]  (value not drawn)
3  5000  [Keystone5000]  (value not drawn)
4  5000  [Keystone5000]  (value not drawn)
C75  Cap_F: 4.7µF  VDC_V: 16V  [0603]  (hidden comment: GRM188Z71C475KE21D)
C76  VDC_V: 25V  ValueDisplayed: 0.1uF  [0402]  (hidden comment: GRM155R71E104KE14D)
C77  Cap_F: 1µF  VDC_V: 25V  [0805_HV]  (hidden comment: GRM219R71E105KA88D)
C78  ValueDisplayed: 1000pF  VDC_V: 50V  [0402]  (hidden comment: CL05B102KB5NNNC)
C79  VDC_V: 25V  ValueDisplayed: 0.1uF  [0402]  (hidden comment: GRM155R71E104KE14D)
C80  VDC_V: 25V  ValueDisplayed: 0.1uF  [0402]  (hidden comment: GRM155R71E104KE14D)
C81  ValueDisplayed: 1000pF  VDC_V: 50V  [0402]  (hidden comment: CL05B102KB5NNNC)
C82  ValueDisplayed: 1000pF  VDC_V: 50V  [0402]  (hidden comment: CL05B102KB5NNNC)
C83  ValueDisplayed: 1000pF  VDC_V: 50V  [0402]  (hidden comment: CL05B102KB5NNNC)
C84  ValueDisplayed: 1000pF  VDC_V: 50V  [0402]  (hidden comment: CL05B102KB5NNNC)
C85  ValueDisplayed: 1000pF  VDC_V: 50V  [0402]  (hidden comment: CL05B102KB5NNNC)
C86  Cap_F: 1µF  VDC_V: 16V  [0603]  (hidden comment: 885012206052)
C87  Cap_F: 1µF  VDC_V: 16V  [0603]  (hidden comment: 885012206052)
C88  ValueDisplayed: 1000pF  VDC_V: 50V  [0402]  (hidden comment: CL05B102KB5NNNC)
C89  ValueDisplayed: 1000pF  VDC_V: 50V  [0402]  (hidden comment: CL05B102KB5NNNC)
C90  ValueDisplayed: 1000pF  VDC_V: 50V  [0402]  (hidden comment: CL05B102KB5NNNC)
C91  ValueDisplayed: 1000pF  VDC_V: 50V  [0402]  (hidden comment: CL05B102KB5NNNC)
C92  VDC_V: 25V  ValueDisplayed: 0.1uF  [0402]  (hidden comment: GRM155R71E104KE14D)
C93  Cap_F: 1µF  VDC_V: 16V  [0603]  (hidden comment: CGA3E1X7R1C105K080AC)
C94  ValueDisplayed: 1000pF  VDC_V: 50V  [0402]  (hidden comment: CL05B102KB5NNNC)
C95  VDC_V: 25V  ValueDisplayed: 0.1uF  [0402]  (hidden comment: GRM155R71E104KE14D)
C96  VDC_V: 25V  ValueDisplayed: 0.033uF  [0402]  (hidden comment: GRM155R71E333KA88D)
C97  ValueDisplayed: 470pF  [0402]  (hidden comment: CGA2B2X7R1H471K050BA)
C98  VDC_V: 50V  ValueDisplayed: 100pF  [0402]  (hidden comment: CC0402JRNPO9BN101)
C99  ValueDisplayed: 1000pF  VDC_V: 50V  [0402]  (hidden comment: CL05B102KB5NNNC)
C100  ValueDisplayed: 1000pF  VDC_V: 50V  [0402]  (hidden comment: CL05B102KB5NNNC)
C102  Cap_F: 4.7µF  VDC_V: 16V  [0603]  (hidden comment: GRM188Z71C475KE21D)
C103  VDC_V: 25V  ValueDisplayed: 0.1uF  [0402]  (hidden comment: GRM155R71E104KE14D)
C104  Cap_F: 4.7nF  VDC_V: 100V  [0603]  (hidden comment: GCM188R72A472KA37D)
C107  VDC_V: 50V  ValueDisplayed: 100pF  [0402]  (hidden comment: CC0402JRNPO9BN101)
C108  VDC_V: 50V  ValueDisplayed: 100pF  [0402]  (hidden comment: CC0402JRNPO9BN101)
C110  VDC_V: 25V  ValueDisplayed: 0.1uF  [0402]  (hidden comment: GRM155R71E104KE14D)
C112  VDC_V: 25V  ValueDisplayed: 0.1uF  [0402]  (hidden comment: GRM155R71E104KE14D)
C128  ValueDisplayed: 47uF  Value2: 16V  [1210_270]  (hidden comment: GRM32ER61C476KE15L)
C129  ValueDisplayed: 47uF  Value2: 16V  [1210_270]  (hidden comment: GRM32ER61C476KE15L)
C130  Cap_F: 1µF  VDC_V: 25V  [0805_HV]  (hidden comment: GRM219R71E105KA88D)
C131  ValueDisplayed: 22µF  VDC_V: 16V  [0805_HV]  (hidden comment: CL21A226KOQNNNE)
C140  ValueDisplayed: 0.1uF  [0402]  (hidden comment: C1005X7R1H104K050BB)
C141  ValueDisplayed: 0.1uF  [0402]  (hidden comment: C1005X7R1H104K050BB)
C142  Cap_F: 1µF  VDC_V: 25V  [0603S]  (hidden comment: CGA3E1X7R1E105K080AC)
C143  VDC_V: 25V  ValueDisplayed: 0.1uF  [0402]  (hidden comment: GRM155R71E104KE14D)
C144  VDC_V: 25V  ValueDisplayed: 0.1uF  [0402]  (hidden comment: GRM155R71E104KE14D)
C149  VDC_V: 25V  ValueDisplayed: 0.1uF  [0402]  (hidden comment: GRM155R71E104KE14D)
C150  VDC_V: 25V  ValueDisplayed: 0.1uF  [0402]  (hidden comment: GRM155R71E104KE14D)
C151  VDC_V: 25V  ValueDisplayed: 0.1uF  [0402]  (hidden comment: GRM155R71E104KE14D)
D5  NUP2105LT1G  value 24V  [SOT-23]
HV_SW1#1  0312-0-15-15-34-27-10-0  [Mill-Max_0312-0-15-15-34-27-10-0]  (value not drawn)
HV_SW1#2  0312-0-15-15-34-27-10-0  [Mill-Max_0312-0-15-15-34-27-10-0]  (value not drawn)
HV_SW2#1  0312-0-15-15-34-27-10-0  [Mill-Max_0312-0-15-15-34-27-10-0]  (value not drawn)
HV_SW2#2  0312-0-15-15-34-27-10-0  [Mill-Max_0312-0-15-15-34-27-10-0]  (value not drawn)
HVBUS1  0312-0-15-15-34-27-10-0  [Mill-Max_0312-0-15-15-34-27-10-0]  (value not drawn)
HVBUS2  0312-0-15-15-34-27-10-0  [Mill-Max_0312-0-15-15-34-27-10-0]  (value not drawn)
HVBUS#1  0312-0-15-15-34-27-10-0  [Mill-Max_0312-0-15-15-34-27-10-0]  (value not drawn)
HVBUS#2  0312-0-15-15-34-27-10-0  [Mill-Max_0312-0-15-15-34-27-10-0]  (value not drawn)
J3  M50-3000445  [FP-M50-3000445_CONN_SCKT_STRP8-MFG]  (parts A,B of 2)
J4  61300511021  [Wurth_61300511021]
J5  HSEC8-160-01-L-DV-A-BL  [controlCARD-120HSEC]
J6  M50-3000445  [FP-M50-3000445_CONN_SCKT_STRP8-MFG]  (parts A,B of 2)
J7  801-41-003-10-001000  [Mill-Max_801-41-003-10-001000]
J8  801-41-003-10-001000  [Mill-Max_801-41-003-10-001000]
J9  LPPB061NFSC-RC  [Sullins_LPPB061NFSC-RC]
J10  GRPB041VWVN-RC  [Sullins_GRPB041VWVN-RC]
L2  ValueDisplayed: 100uH  [ACT45B]  (hidden comment: ACT45B-101-2P-TL003)
L7  Ind_H: 2.2µH  [FP-74438336010_SMD2-MFG]  (hidden comment: 74438336022)
PGND1  0312-0-15-15-34-27-10-0  [Mill-Max_0312-0-15-15-34-27-10-0]  (value not drawn)
PGND2  0312-0-15-15-34-27-10-0  [Mill-Max_0312-0-15-15-34-27-10-0]  (value not drawn)
PGND#1  0312-0-15-15-34-27-10-0  [Mill-Max_0312-0-15-15-34-27-10-0]  (value not drawn)
PGND#2  0312-0-15-15-34-27-10-0  [Mill-Max_0312-0-15-15-34-27-10-0]  (value not drawn)
R22  ValueDisplayed: 100  [0402]  (hidden comment: CRCW0402100RFKED)
R23  ValueDisplayed: 100  [0402]  (hidden comment: CRCW0402100RFKED)
R26  ValueDisplayed: 0  [0402]  (hidden comment: RC0402JR-070RL)
R28  ValueDisplayed: 100  [0402]  (hidden comment: CRCW0402100RFKED)
R29  ValueDisplayed: 100  [0402]  (hidden comment: CRCW0402100RFKED)
R30  ValueDisplayed: 0  [0402]  (hidden comment: RC0402JR-070RL)
R31  ValueDisplayed: 100  [0402]  (hidden comment: CRCW0402100RFKED)
R32  ValueDisplayed: 0  [0603]  (hidden comment: RC0603JR-070RL)
R33  ValueDisplayed: 60  [1206]  (hidden comment: CRCW120660R0KNEAIF)
R34  ValueDisplayed: 0  [0603]  (hidden comment: MCT06030Z0000ZP500)
R35  ValueDisplayed: 0  [0603]  (hidden comment: RC0603JR-070RL)
R36  ValueDisplayed: 60  [1206]  (hidden comment: CRCW120660R0KNEAIF)
R67  ValueDisplayed: 10.0k  [0402]  (hidden comment: Resistor)
R70  ValueDisplayed: 10.0  [0603]  (hidden comment: CRCW060310R0FKEA)
R72  ValueDisplayed: 10.0  [0603]  (hidden comment: CRCW060310R0FKEA)
R74  ValueDisplayed: 0  [0603]  (hidden comment: MCT06030Z0000ZP500)
R76  ValueDisplayed: 100  [0402]  (hidden comment: CRCW0402100RFKED)
R84  ValueDisplayed: 100  [0402]  (hidden comment: CRCW0402100RFKED)
R85  ValueDisplayed: 100  [0402]  (hidden comment: CRCW0402100RFKED)
R86  ValueDisplayed: 100  [0402]  (hidden comment: CRCW0402100RFKED)
R89  ValueDisplayed: 100  [0402]  (hidden comment: CRCW0402100RFKED)
R97  ValueDisplayed: 100  [0402]  (hidden comment: CRCW0402100RFKED)
R98  ValueDisplayed: 100  [0402]  (hidden comment: CRCW0402100RFKED)
R101  ValueDisplayed: 100  [0402]  (hidden comment: CRCW0402100RFKED)
R102  ValueDisplayed: 100  [0402]  (hidden comment: CRCW0402100RFKED)
R104  ValueDisplayed: 100  [0402]  (hidden comment: CRCW0402100RFKED)
R105  ValueDisplayed: 100  [0402]  (hidden comment: CRCW0402100RFKED)
RT1  TMP6131DECR  [DEC0002A]
U6  INA199A2DCKT  [DCK0006A_N]
U7  TLV76733DRVT  [DRV0006A-MFG]
U8  ISO7742DWR  [DW0016B_HV]
U9  TCAN1042HDRBRQ1  [DRB0008F]
U16  TPS62163DSGR  [DSG0008A]
U19  TLV71333PQDBVRQ1  [DBV0005A_N]
U20  REF2033AIDDCR  [DDC0005A_N]

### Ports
1V65 (in), 1V65 (out), 3.3Vp, 3.3Vp (out), 3.3Vref (out), 3.3Vs, 3.3Vs (in), 3.3Vs (out), 5Vs, 5Vs (in), 5Vs (out), 12Vp, 12Vs, 12Vs (in), 48Vo-, Bot_ZVD1 (in), Bot_ZVD2 (in), CAN_RX, CAN_RX (out), CAN_TX, CAN_TX (in), CANH (in), CANL (in), HV_PWM1H (in), HV_PWM1L (in), HV_PWM2H (in), HV_PWM2L (in), HV_SW1, HV_SW2, HVBUS (out), ISNS_PRI (in), ISNS_PRI_TANK (in), ISNS_SEC (in), ISNS_SEC (out), ISNS_SEC_TANK (in), LV_PWM1H (in), LV_PWM1L (in), LV_PWM2H (in), LV_PWM2L (in), SCI_RX0_Pri (in), SCI_RX0_Pri (out), SCI_RX0_Sec (in), SCI_RX0_Sec (out), SCI_RXCLK_Sec (out), SCI_TX0_Pri (in), SCI_TX0_Pri (out), SCI_TX0_Sec (in), SCI_TX0_Sec (out), SCI_TXCLK_Pri (in), SCI_TXCLK_Pri (out), TMP_SEC (in), TMP_SEC (out), Top_ZVD1 (in), Top_ZVD2 (in), VSNS_PRI (in), VSNS_SEC (in)

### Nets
PGND: 1.1 C75.1 C76.2 C77.2 C86.2 C90.2 C91.2 C141.2 J4.5 J7.2 J8.2 PGND1.1 PGND2.1 PGND#1.1 PGND#2.1 U7.3(GND) U7.5(GND) U7.7(Thermal_Pad) U8.2(GND1) U8.8(GND1)
SGND: 2.1 C78.1 C79.2 C80.2 C81.2 C82.2 C83.2 C84.2 C85.2 C87.1 C88.2 C89.2 C92.1 C93.1 C94.2 C95.2 C97.2 C98.2 C99.2 C100.2 C102.2 C103.1 C104.1 C107.2 C108.1 C110.2 C112.2 C128.1 C129.1 C130.2 C131.2 C140.1 C142.2 C143.2 C144.2 C149.2 C150.2 C151.2 D5.3 J3.2 J3.4 J3.6 J5.7 J5.10 J5.22 J5.29 J5.35 J5.38 J5.46 J5.47 J5.65 J5.83 J5.97 J5.111 J6.2 J6.4 J6.6 J9.6 J10.4 R70.1 RT1.1 U6.2(GND) U8.9(GND2) U8.15(GND2) U9.2(GND) U9.9(PAD) U16.1(PGND) U16.4(AGND) U16.5(FB) U16.9(EP) U19.2(GND) U20.2(GND)  [also labelled DGND]
1V65: C151.1 U6.1(REF) U20.1(VBIAS) ; port 1V65
3.3Vp: C75.2 C76.1 C86.1 C141.1 U7.1(OUT) U7.2(SNS) U8.1(VCC1) ; port 3.3Vp
3.3Vref: C150.1 U20.5(VREF) ; port 3.3Vref
3.3Vs: C87.2 C92.2 C93.2 C140.2 C142.1 C143.1 R67.1 U6.3(V+) U8.16(VCC2) U19.5(OUT) ; port 3.3Vs
5Vs: C95.1 C102.1 C131.1 C144.1 C149.1 J3.8 J5.48 J5.84 J5.98 J5.112 J6.8 L7.2 U9.3(VCC) U16.6(VOS) U19.1(IN) U19.3(EN) U20.3(EN) U20.4(VIN) ; port 5Vs
12Vp: 3.1 C77.1 J7.3 J8.3 U7.4(EN) U7.6(IN) ; port 12Vp
12Vs: 4.1 C128.2 C129.2 C130.1 J9.1 U16.2(VIN) U16.3(EN) ; port 12Vs
48Vo-: R72.1 ; port 48Vo-
Bot_ZVD1: J3.1 R102.1 ; port Bot_ZVD1
Bot_ZVD2: J6.1 R97.1 ; port Bot_ZVD2
CAN_RX: J5.70 U9.4(RXD) ; port CAN_RX
CAN_TX: J5.68 U9.1(TXD) ; port CAN_TX
CANH: D5.1 J10.1 R32.2 ; port CANH
CANL: D5.2 J10.2 R35.2 ; port CANL
HV_PWM1H: J3.7 J5.49 ; port HV_PWM1H
HV_PWM1L: J3.5 J5.51 ; port HV_PWM1L
HV_PWM2H: J5.53 J6.7 ; port HV_PWM2H
HV_PWM2L: J5.55 J6.5 ; port HV_PWM2L
HV_SW1: HV_SW1#1.1 HV_SW1#2.1 ; port HV_SW1
HV_SW2: HV_SW2#1.1 HV_SW2#2.1 ; port HV_SW2
HVBUS: HVBUS1.1 HVBUS2.1 HVBUS#1.1 HVBUS#2.1 ; port HVBUS
ISNS_PRI: R84.1 ; port ISNS_PRI
ISNS_PRI_TANK: R86.1 ; port ISNS_PRI_TANK
ISNS_SEC: C98.1 R23.2 U6.6(OUT) ; port ISNS_SEC
ISNS_SEC_TANK: R76.2 ; port ISNS_SEC_TANK
LV_PWM1H: J5.50 J9.2 ; port LV_PWM1H
LV_PWM1L: J5.52 J9.3 ; port LV_PWM1L
LV_PWM2H: J5.54 J9.4 ; port LV_PWM2H
LV_PWM2L: J5.56 J9.5 ; port LV_PWM2L
SCI_RX0_Pri: J4.3 U8.5(OUTC) ; port SCI_RX0_Pri
SCI_RX0_Sec: R29.2 U8.13(OUTB) ; port SCI_RX0_Sec
SCI_RXCLK_Sec: R28.2 U8.14(OUTA) ; port SCI_RXCLK_Sec
SCI_TX0_Pri: J4.2 R104.2 ; port SCI_TX0_Pri
SCI_TX0_Sec: J5.75 R105.1 ; port SCI_TX0_Sec
SCI_TXCLK_Pri: J4.1 R31.2 ; port SCI_TXCLK_Pri
TMP_SEC: C97.1 R67.2 R89.1 RT1.2 ; port TMP_SEC
Top_ZVD1: J3.3 R101.1 ; port Top_ZVD1
Top_ZVD2: J6.3 R98.1 ; port Top_ZVD2
VSNS_PRI: R85.2 ; port VSNS_PRI
VSNS_SEC: R22.2 ; port VSNS_SEC
NetC78_2: C78.2 J5.31 R86.2
NetC79_1: C79.1 J5.25 R84.2
NetC80_1: C80.1 J5.20 R23.1
NetC81_1: C81.1 J5.30 R76.1
NetC82_1: C82.1 J5.71 R28.1
NetC83_1: C83.1 J5.73 R29.1
NetC84_1: C84.1 J5.86 R97.2
NetC85_1: C85.1 J5.88 R98.2
NetC88_1: C88.1 J5.103 R101.2
NetC89_1: C89.1 J5.105 R102.2
NetC90_1: C90.1 R104.1 U8.4(INB)
NetC91_1: C91.1 R31.1 U8.3(INA)
NetC94_1: C94.1 R105.2 U8.12(INC)
NetC96_1: C96.1 C100.1 R70.2 U6.5(IN-)
NetC96_2: C96.2 C99.1 R72.2 U6.4(IN+)
NetC103_2: C103.2 J5.34 R89.2
NetC104_2: C104.2 C107.1 C108.2 R32.1 R33.1 R35.1 R36.1
NetC110_1: C110.1 J5.23 R85.1
NetC112_1: C112.1 J5.14 R22.1
NetJ4_4: J4.4 R74.2
NetJ5_69: J5.69 R26.2
NetJ5_72: J5.72 R30.1
NetL2_1: L2.1 U9.6(CANL)
NetL2_2: L2.2 U9.7(CANH)
NetL2_3: L2.3 R33.2
NetL2_4: L2.4 R36.2
NetL7_1: L7.1 U16.7(SW)
NetR34_2: R34.2 U9.8(STB)

Not connected (* = marked no-connect by the designer): J5 1* 2* 3* 4* 5* 6* 8* 9* 11* 12* 13* 15* 16* 17* 18* 19* 21* 24* 26* 27* 28* 32* 33* 36* 37* 39* 40* 41* 42* 43* 44* 45* 57* 58* 59* 60* 61* 62* 63* 64* 66* 67* 74* 76* 77* 78* 79* 80* 81* 82* 85* 87* 89* 90* 91* 92* 93* 94* 95* 96* 99 100* 101 102* 104* 106* 107* 108* 109* 110* 113* 114* 115* 116* 117* 118* 119* 120*; J7 1*; J8 1*; J10 3*; R26 1*; R30 2*; R34 1*; R74 1*; U8 6(OUTD)* 7(EN1)* 10(EN2)* 11(IND)*; U9 5(NC)*; U16 8(PG); U19 4(NC)*

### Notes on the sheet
- 2.9V/100A
- NC
- (near U19) 150mA
- (near 3) 12Vp
- (near 4) 12Vs

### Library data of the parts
1 2 = CMP-0055138-1: Test Point, Miniature, Black, TH; Manufacturer: Keystone; ContactFinish: Silver; Green_Lifecycle: Active; Green_REACh: Passed; CNHeader: FALSE; CT: TRUE
3 4 = CMP-0055137-1: Test Point, Miniature, Red, TH; Manufacturer: Keystone; ContactFinish: Silver; Green_Lifecycle: Active; Green_REACh: Passed; CNHeader: FALSE; CT: TRUE
C75 C102 = CMP-0064936-4: CAP, CERM, 4.7 uF, 16 V,+/- 10%, X7R, 0603; Manufacturer: MuRata; TaMin_C: -55°C; Polarized: N; SizeAreaWB_mm2: 4.68; Value1: Unknown; U/M: EA; Value: 4.7uF; TaMax_C: 125°C; SizeZ_mm: 1; SizeX_mm: 1.6; SizeY_mm: 0.8; SizeArea_mm2: 1.28; AEC Category: Q200
C76 C79 C80 C92 C95 C103 C110 C112 C143 C144 C149-C151 = CMP-0006659-2: as C24 on sheet PMP41134_sheet1
C77 C130 = CMP-0008217-2: CAP, CERM, 1 uF, 25 V, +/- 10%, X7R, 0805; Manufacturer: MuRata; TaMin_C: -55°C; Polarized: N; SizeAreaWB_mm2: 6.75; Value1: Unknown; U/M: EA; Value: 1uF; TaMax_C: 125°C; SizeZ_mm: 1.45; SizeX_mm: 2; SizeY_mm: 1.25; Cap_Case: 0805; SizeArea_mm2: 2.5; AEC Category: Q200
C78 C81-C85 C88-C91 C94 C99 C100 = CMP-0860560-1: CAP, CERM, 1000 pF, 50 V,+/- 10%, X7R, 0402; Manufacturer: Samsung Electro-Mechanics; SizeArea_mm2: 0.5; TaMin_C: -55°C; AEC Qualified: N; TaMax_C: 125°C; SizeZ_mm: 0.6; Green_Lifecycle: Active; Green_REACh: Incomplete; SizeX_mm: 1; Cap_F: 1nF; AEC Category: Q200; SizeAreaWB_mm2: 3; Value: 1000pF; U/M: EA
C86 C87 = CMP-0006831-4: CAP, CERM, 1 uF, 16 V, +/- 10%, X7R, 0603; Manufacturer: Wurth Elektronik; TaMin_C: -55°C; Polarized: N; SizeAreaWB_mm2: 4.68; Value1: Unknown; U/M: EA; Value: 1uF; TaMax_C: 125°C; SizeZ_mm: 1; SizeX_mm: 1.6; SizeY_mm: 0.8; SizeArea_mm2: 1.28; AEC Category: Q200
C93 = CMP-0079607-1: as C20 on sheet PMP41134_sheet1
C96 = CMP-0006666-2: CAP, CERM, 0.033 uF, 25 V, +/- 10%, X7R, 0402; Manufacturer: MuRata; TaMin_C: -55°C; Polarized: N; SizeAreaWB_mm2: 3; Value1: Unknown; U/M: EA; TaMax_C: 125°C; SizeZ_mm: 0.6; SizeX_mm: 1; SizeY_mm: 0.5; Cap_F: 33nF; AEC Category: Q200
C97 = CMP-0006320-2: CAP, CERM, 470 pF, 50 V, +/- 10%, X7R, AEC-Q200 Grade 1, 0402; Manufacturer: TDK; TaMin_C: -55°C; ESR_ohm: 4.96489; Polarized: N; SizeAreaWB_mm2: 3; Value1: 4.96489 ohm; U/M: EA; Value: 470pF; TaMax_C: 125°C; SizeZ_mm: 0.6; SizeX_mm: 1; SizeY_mm: 0.5; Value2: 50V; CompType: Capacitor; AEC Qualified: Y; IRMS_A: 2.28414dA; AEC Category: Q200
C98 C107 C108 = CMP-0006303-2: CAP, CERM, 100 pF, 50 V, +/- 5%, C0G/NP0, 0402; Manufacturer: Yageo America; TaMin_C: -55°C; Polarized: N; SizeAreaWB_mm2: 3; Value1: Unknown; U/M: EA; Value: 100pF; TaMax_C: 125°C; SizeZ_mm: 0.6; SizeX_mm: 1; SizeY_mm: 0.5; AEC Category: Q200
C104 = CMP-0079247-1: CAP, CERM, 4700 pF, 100 V,+/- 10%, X7R, AEC-Q200 Grade 1, 0603; Manufacturer: MuRata; SizeAreaWB_mm2: 4.68; SizeArea_mm2: 1.28; AEC Qualified: Y; AEC Category: Q200; Value: 4700pF; TaMax_C: 125°C; SizeZ_mm: 1; Polarized: N; TaMin_C: -55°C; SizeY_mm: 0.8; U/M: EA; SizeX_mm: 1.6
C128 C129 = CMP-0009211-2: CAP, CERM, 47 uF, 16 V, +/- 10%, X5R, 1210; Manufacturer: MuRata; Polarized: N; Value: 47uF; U/M: EA; Cap_F: 47µF; Value1: Unknown; TaMin_C: -55°C; TaMax_C: 85°C; Cap_Case: 1210; SizeArea_mm2: 8; SizeAreaWB_mm2: 14.7; SizeX_mm: 3.2; SizeY_mm: 2.5; SizeZ_mm: 2.7; AEC Category: Q200
C131 = CMP-0085852-1: CAP, CERM, 22 µF, 16 V,+/- 10%, X5R, 0805; Manufacturer: Samsung Electro-Mechanics; SizeX_mm: 2; TaMax_C: 85°C; AEC Category: Q200; SizeY_mm: 1.25; TaMin_C: -55°C; SizeZ_mm: 1.45; U/M: EA; Polarized: N; SizeArea_mm2: 2.5; Cap_Case: 0805; SizeAreaWB_mm2: 6.75; Value: 22uF
C140 C141 = CMP-0006297-2: CAP, CERM, 0.1 uF, 50 V, +/- 10%, X7R, 0402; Manufacturer: TDK; Alternate PartNumber: 885012205037; Alternate Manufacturer: Wurth Elektronik; Polarized: N; Value: 0.1uF; U/M: EA; Cap_F: 100nF; ESR_ohm: 0.039064; Value1: 0.039064 ohm; VDC_V: 50V; IRMS_A: 8.14669dA; TaMin_C: -55°C; TaMax_C: 125°C; SizeArea_mm2: 0.5; SizeAreaWB_mm2: 3; SizeX_mm: 1; SizeZ_mm: 0.6; AEC Category: Q200
C142 = CMP-0076705-3: CAP, CERM, 1 µF, 25 V,+/- 10%, X7R, AEC-Q200 Grade 1, 0603; Manufacturer: TDK; SizeAreaWB_mm2: 4.68; SizeArea_mm2: 1.28; AEC Qualified: Y; AEC Category: Q200; Value: 1uF; TaMax_C: 125°C; SizeZ_mm: 1.0; AEC Grade: 1; Polarized: N; TaMin_C: -55°C; SizeY_mm: 0.8; U/M: EA; SizeX_mm: 1.6; Cap_Case: 1.6x0.8x0.8mm
D5 = CMP-0005919-3: Diode, TVS, Bi, 24 V, SOT-23; Manufacturer: ON Semiconductor; SizeAreaWB_mm2: 14; Value1: 350W; SizeZ_mm: 1.1; SizeX_mm: 2.5; SizeY_mm: 3; SizeArea_mm2: 7.5; AEC Category: Q101
HV_SW1#1 HV_SW1#2 HV_SW2#1 HV_SW2#2 HVBUS1 HVBUS2 HVBUS#1 HVBUS#2 PGND1 PGND2 PGND#1 PGND#2 = CMP-0055026-1: Manufacturer: Mill-Max; CNHeader: FALSE; Green_Lifecycle: Active; Gender: Female; Green_REACh: Passed; CompType: Pin Receptacle; ContactFinish: Gold
J3 J6 = CMP-0097755-1: Conn Socket Strip SKT 8 POS 1.27mm Solder ST Thru-Hole; Manufacturer: Harwin; Conn Orientation: Vertical; Conn Gender: Female; Current_A: 1A; AEC Qualified: No; Is Female: yes; ContactFinish: Gold,Nickel; SizeZ_mm: 4.55mm; Row_Count: 2
J4 = CMP-0054800-1: Header, 2.54 mm, 5x1, Gold, R/A, TH; Manufacturer: Wurth Elektronik; CNHeader: TRUE; Shrouded: N; Gender: Male; Row_Count: 1; Pitch_mm: 2.54; CT: FALSE
J5 = CMP-0003814-2: C2000 controlCARD-120HSEC connector, SMT; Manufacturer: Samtec; Note: The pin numbering does not match Samtec datasheet
J7 J8 = CMP-0076709-1: Receptacle, 2.54mm, 3x1, Gold, TH; Manufacturer: Mill-Max; Pitch_mm: 2.54; Gender: Female; CT: True; Row_Count: 1; CompType: Socket Strip; CNHeader: False
J9 = CMP-0054652-1: Receptacle, 1.27mm, 6x1, Gold, SMT; Manufacturer: Sullins Connector Solutions; CNHeader: FALSE; Gender: Female; CompType: Socket Strip; Row_Count: 1; Pitch_mm: 1.27; CT: TRUE
J10 = CMP-0054569-1: Header, 50mil, 4x1, Gold, TH; Manufacturer: Sullins Connector Solutions; CNHeader: TRUE; Green_Lifecycle: Not Set; Green_REACh: Incomplete; CT: FALSE
L2 = CMP-0062430-2: Inductor, Ferrite, 100 uH, 0.15 A, 2 ohm, SMD; Manufacturer: TDK; Isat: 0.15A @ % inductance drop; Green_Lifecycle: Active; SizeAreaWB_mm2: 23.1; DCR_ohm: 2; Green_REACh: Passed; Value1: 2 ohm; Value: 100uH; Imax_A: 1.5dA; SizeZ_mm: 3; SizeX_mm: 4.5; SizeY_mm: 3.2; Value2: 0.15A; SizeArea_mm2: 14.4; Ind_H: 100µH; AEC Category: Q200
L7 = CMP-0087867-1: 2.2µH Shielded Molded Inductor 2.4A 67mOhm Max 2-SMD; Manufacturer: Wurth Electronics; SizeZ_mm: 2mm; Material: Metal Composite; Isat: 4.3A; Symbol Name: SYM-74438336010; DCR_ohm: 0.032; AEC Grade: Grade 1; AEC Qualified: Yes
R22 R23 R28 R29 R31 R76 R84-R86 R89 R97 R98 R101 R102 R104 R105 = CMP-0025951-1: RES, 100, 1%, 0.063 W, 0402; Manufacturer: Vishay-Dale; Power_W: 63mW; TempCo: 100 ppm/C; Value_Code: 100R; U/M: EA; Value: 100; EIA_Code: E96; SizeX_mm: 1; SizeY_mm: 0.5; SizeZ_mm: 0.6; Value2: 0.063W; VDC_V: 50V; AEC Category: Q200
R26 R30 = CMP-0027004-2: RES, 0, 5%, 0.063 W, 0402; Manufacturer: Yageo America; Power_W: 63mW; TempCo: 200 ppm/C; Value_Code: 0000; U/M: EA; Value: 0; EIA_Code: E24; SizeX_mm: 1; SizeY_mm: 0.5; SizeZ_mm: 0.6; Value2: 0.063W; VDC_V: 50V; AEC Category: Q200
R32 R35 = CMP-0025885-5: RES, 0, 5%, 0.1 W, 0603; Manufacturer: Yageo; Power_W: 100mW; TempCo: 200 ppm/C; Value_Code: 0000; Value: 0; EIA_Code: E24; SizeX_mm: 1.6; SizeZ_mm: 1; Value2: 0.1W; SizeArea_mm2: 1.28; AEC Qualified: N; VDC_V: 75V; AEC Category: Q200; SizeY_mm: 0.8; SizeAreaWB_mm2: 4.68
R33 R36 = CMP-0018709-3: RES, 60, 10%, 0.25 W, AEC-Q200 Grade 0, 1206; Manufacturer: Vishay-Dale; Power_W: 250mW; TempCo: 200 ppm/C; Value_Code: 60R0; Value: 60; SizeX_mm: 3.2; SizeY_mm: 1.6; SizeZ_mm: 1.35; Value2: 0.25W; SizeArea_mm2: 5.12; AEC Qualified: Y; AEC Grade: 0; AEC Category: Q200
R34 R74 = CMP-0025884-2: as R6 on sheet PMP41134_sheet1
R67 = CMP-0025958-3: RES, 10.0 k, 1%, 0.063 W, AEC-Q200 Grade 0, 0402; PartNumber: CRCW040210K0FKED; Manufacturer: Vishay-Dale; Value: 10.0k; Res_ohm: 10k; Value_Code: 10k0; Power_W: 63mW; Value2: 0.063W; VDC_V: 50V; TempCo: 100 ppm/C; SizeArea_mm2: 0.5; SizeX_mm: 1; SizeZ_mm: 0.6; EIA_Code: E96; AEC Category: Q200; AEC Qualified: Y; AEC Grade: 0
R70 R72 = CMP-0022003-4: as R18 on sheet PMP41134_sheet1
RT1 = CMP-0084566-1: Thermistor, DEC0002A (X1SON-2); Alternate Manufacturer: Texas Instruments; Alternate PartNumber: TMP6131DECT; CompType: IC; AEC Category: Q200; SizeX_mm: 1; AEC Qualified: N; SizeZ_mm: 0.5; SizeArea_mm2: 0.6; SizeAreaWB_mm2: 3.2
U6 = CMP-0037966-3: 26-V, Bi-Directional, Zero-Drift, Low- or High-Side, Voltage Output Current Shunt Monitor, DCK0006A (SOT-SC70-6); Manufacturer: Texas Instruments; Vs(Min)(V): 2.7; Input Offset (+/-)(Max)(uV): 150; Quiescent Current (+/-)(Typ)(mA): 0.065; Common Mode Range(Min)(V): -0.3; Gain(V/V): 100; Eco-Plan: Green (RoHS & no Sb/Br); Input Offset Drift (+/-)(Max)(uV/Degrees Celsius): 0.5; Rating: Catalog; Vs(Max)(V): 26; Small-Signal Bandwidth(Typ)(MHz): 0.03; AEC Category: Q200; AEC Qualified: N; CompType: IC; SizeAreaWB_mm2: 9.3; SizeArea_mm2: 4.2; SizeX_mm: 2.1; SizeY_mm: 2.0; SizeZ_mm: 1.1
U7 = CMP-0090734-1: Linear Voltage Regulator IC  1 Output  1A 6-WSON (2x2); Manufacturer: Texas Instruments; SizeZ_mm: 0.8mm; Nominal Supply Current: 60uA; TJmax_C: +125°C; Max Supply Voltage: 16V; Number Of Outputs: 1; Accuracy Percentage: 1%; Output Type: Fixed; Output Voltage: 3.3V; Standoff Height: 0mm; Dropout Voltage: 0.9V; AEC Qualified: No; Min Supply Voltage: 2.5V
U8 = CMP-0065839-3: 5.7 kVrms, 100 Mbps, Reinforced 4-Channel 2/2 Digital Isolator, DW0016B (SOIC-16); Manufacturer: Texas Instruments; Alternate PartNumber: ISO7842DW; CompType: IC; SizeY_mm: 10.3; Rating: Catalog; AEC Qualified: N; SizeX_mm: 10.4; SizeZ_mm: 2.65; SizeArea_mm2: 107.12; SizeAreaWB_mm2: 152.52; AEC Category: Q200
U9 = CMP-0065181-3: Automotive Fault Protected CAN Transceiver With Flexible Data-Rate, DRB0008F (VSON-8); Manufacturer: Texas Instruments; Alternate PartNumber: TCAN1042HDRBTQ1; SizeX_mm: 3.0; CompType: IC; SizeZ_mm: 1.0; SizeArea_mm2: 9.0; SizeAreaWB_mm2: 16.0; AEC Category: Q200; AEC Qualified: Y
U16 = CMP-0037791-2: Buck Step Down Regulator with 3 to 17 V Input and 5 V Output, -40 to 85 degC, 8-Pin WSON (DSG), Green (RoHS & no Sb/Br); Manufacturer: Texas Instruments; Vin(Min)(V): 3; Switch Current Limit(Typ)(A): 1.8; Vin(Max)(V): 17; Rating: Catalog; Vout(Min)(V): 5; Regulated Outputs(#): 1; Duty Cycle(Max)(%): 100; SubFamily: Step-Down Regulator; Synchronous Rectification: TRUE; Iq(Typ)(mA): 0.017
U19 = CMP-0073750-1: Capacitor-Free, 150-mA, LDO Regulator w/ Foldback Current Limit, DBV0005A (SOT-23-5); Alternate Manufacturer: Texas Instruments; SizeAreaWB_mm2: 14.82; U/M: EA; SizeZ_mm: 1.45; SizeX_mm: 2.8; SizeY_mm: 2.9; SizeArea_mm2: 8.12; CompType: IC
U20 = CMP-0066190-1: Low-Drift, Low-Power, Dual-Output VREF and VREF/2 Voltage Reference, DDC0005A (SOT-23-T-5); Alternate PartNumber: REF2033AIDDCT; Alternate Manufacturer: Texas Instruments; SizeAreaWB_mm2: 14.82; U/M: EA; SizeZ_mm: 1.1; SizeX_mm: 2.8; SizeY_mm: 2.9; SizeArea_mm2: 8.12; CompType: IC

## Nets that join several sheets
PGND: PMP41134_sheet1 (18 pins), PMP41134_sheet2 (20 pins)
SGND: PMP41134_sheet1 (53 pins), PMP41134_sheet2 (72 pins)
1V65: PMP41134_sheet1 (C42.2 R25.1 U1.3 U1.7), PMP41134_sheet2 (C151.1 U6.1 U20.1)
3.3Vp: PMP41134_sheet1 (6 pins), PMP41134_sheet2 (7 pins)
3.3Vref: PMP41134_sheet1 (C74.2 U5.6), PMP41134_sheet2 (C150.1 U20.5)
3.3Vs: PMP41134_sheet1 (18 pins), PMP41134_sheet2 (10 pins)
48Vo-: PMP41134_sheet1 (R46.2 R49.2 R50.2 R54.2), PMP41134_sheet2 (R72.1)
HV_SW1: PMP41134_sheet1 (U10.1), PMP41134_sheet2 (HV_SW1#1.1 HV_SW1#2.1)
HV_SW2: PMP41134_sheet1 (8 pins), PMP41134_sheet2 (HV_SW2#1.1 HV_SW2#2.1)
HVBUS: PMP41134_sheet1 (7 pins), PMP41134_sheet2 (HVBUS1.1 HVBUS2.1 HVBUS#1.1 HVBUS#2.1)
ISNS_PRI: PMP41134_sheet1 (C25.1 R14.2 U2.1), PMP41134_sheet2 (R84.1)
ISNS_PRI_TANK: PMP41134_sheet1 (U10.6), PMP41134_sheet2 (R86.1)
ISNS_SEC_TANK: PMP41134_sheet1 (U1.5), PMP41134_sheet2 (R76.2)
VSNS_PRI: PMP41134_sheet1 (U5.7), PMP41134_sheet2 (R85.2)
VSNS_SEC: PMP41134_sheet1 (U3.1 U3.2), PMP41134_sheet2 (R22.2)

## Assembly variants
001: not fitted FID1 FID2 FID3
